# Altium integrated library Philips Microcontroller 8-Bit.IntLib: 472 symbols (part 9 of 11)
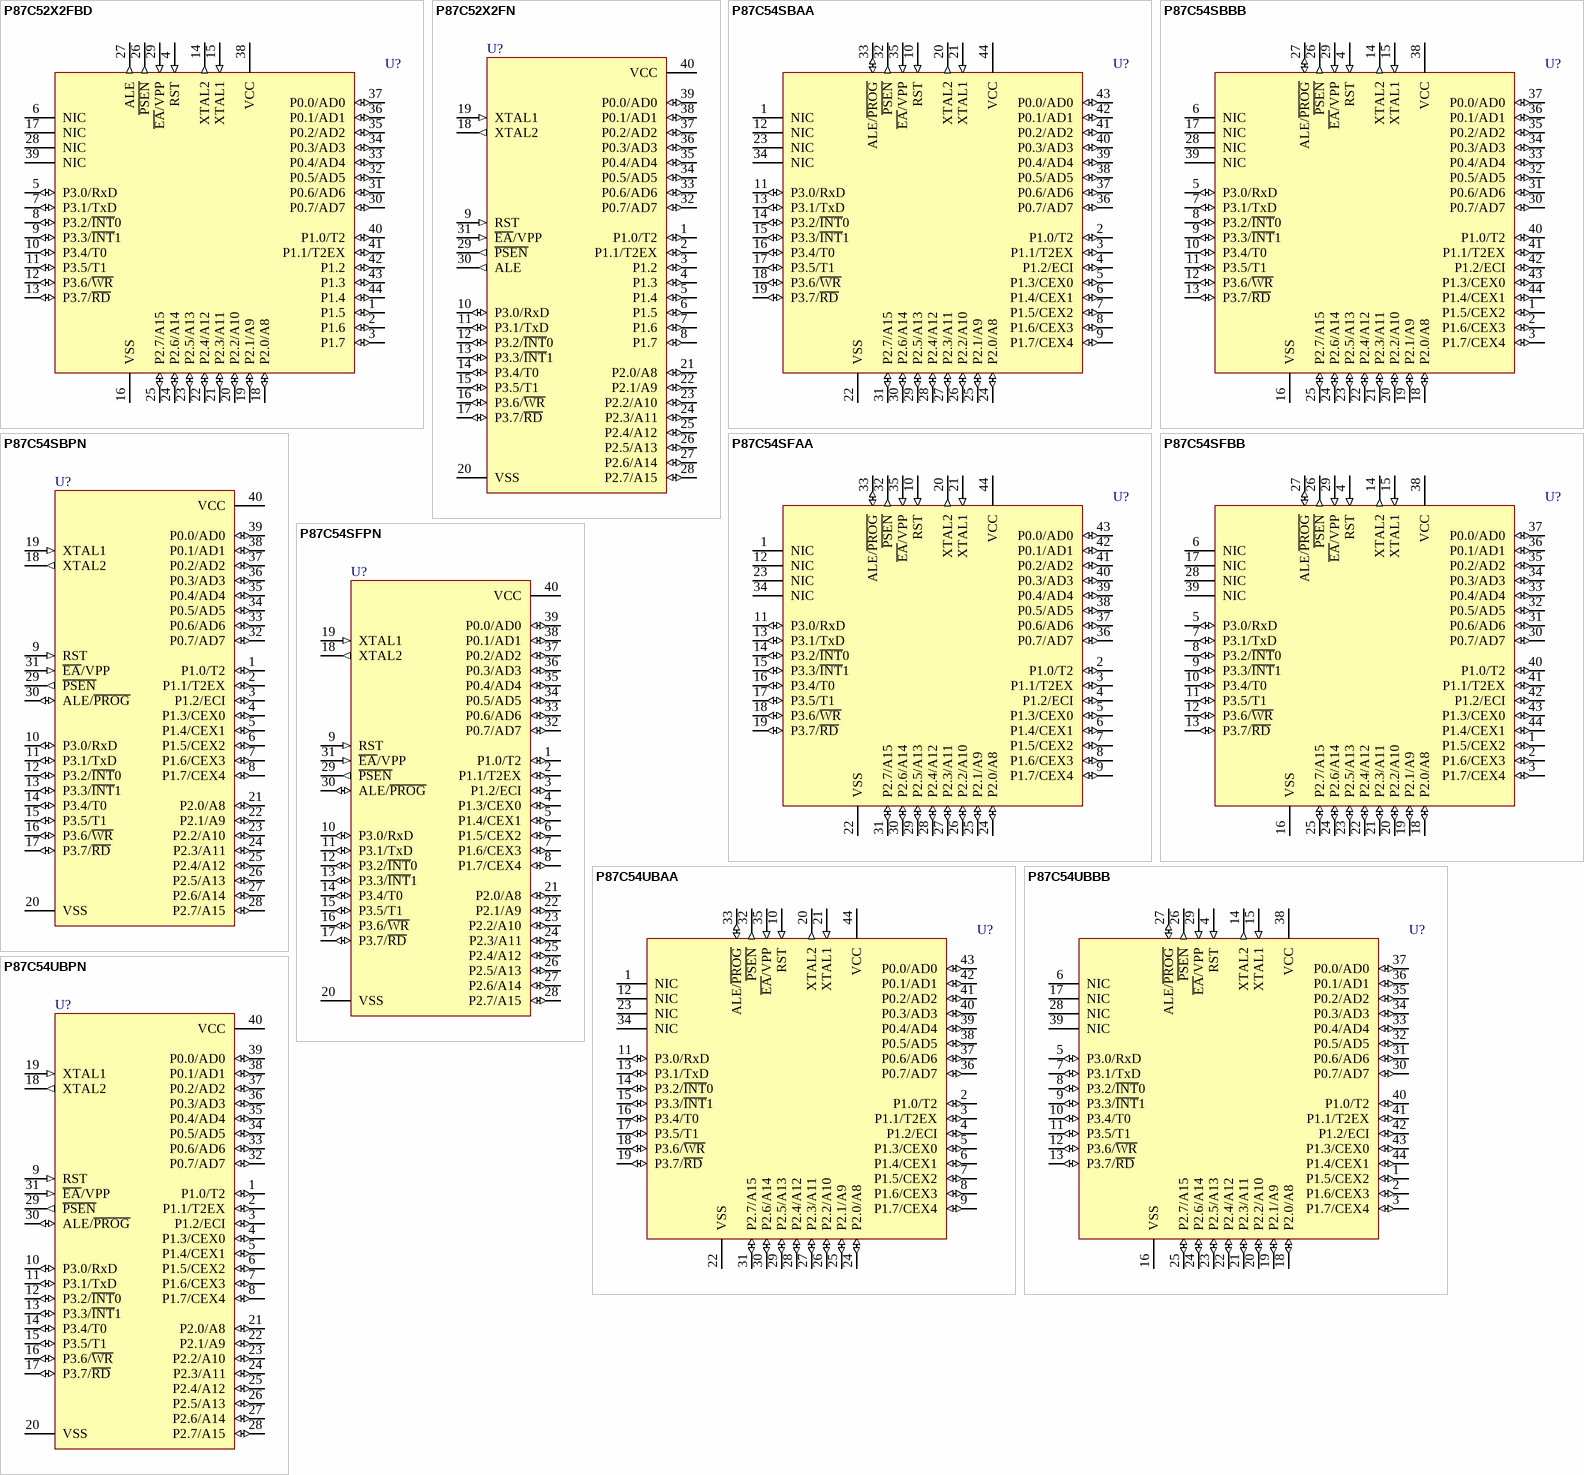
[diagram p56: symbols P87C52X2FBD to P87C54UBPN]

## P87C54SFBB
designator U?
80C51 8-Bit Microcontroller Family: 256 B RAM, 16 kB OTP, 2.7V-5.5V, Low Power, High Speed
footprint SOT307-2_N (QFP, 44-Leads, Body 10x10mm, Pitch 0.8mm, IPC Medium Density)
footprint SOT307-2_L (QFP, 44-Leads, Body 10x10mm, Pitch 0.8mm, IPC High Density)
footprint SOT307-2_M (QFP, 44-Leads, Body 10x10mm, Pitch 0.8mm, IPC Low Density)
pins: 1 P1.5/CEX2 (io), 2 P1.6/CEX3 (io), 3 P1.7/CEX4 (io), 4 RST (in), 5 P3.0/RxD (io), 6 NIC, 7 P3.1/TxD (io), 8 P3.2/~{INT}0 (io), 9 P3.3/~{INT}1 (io), 10 P3.4/T0 (io), 11 P3.5/T1 (io), 12 P3.6/~{WR} (io), 13 P3.7/~{RD} (io), 14 XTAL2 (out), 15 XTAL1 (in), 16 VSS (power), 17 NIC, 18 P2.0/A8 (io), 19 P2.1/A9 (io), 20 P2.2/A10 (io), 21 P2.3/A11 (io), 22 P2.4/A12 (io), 23 P2.5/A13 (io), 24 P2.6/A14 (io), 25 P2.7/A15 (io), 26 ~{PSEN} (out), 27 ALE/~{PROG} (io), 28 NIC, 29 ~{EA}/VPP (in), 30 P0.7/AD7 (io), 31 P0.6/AD6 (io), 32 P0.5/AD5 (io), 33 P0.4/AD4 (io), 34 P0.3/AD3 (io), 35 P0.2/AD2 (io), 36 P0.1/AD1 (io), 37 P0.0/AD0 (io), 38 VCC (power), 39 NIC, 40 P1.0/T2 (io), 41 P1.1/T2EX (io), 42 P1.2/ECI (io), 43 P1.3/CEX0 (io), 44 P1.4/CEX1 (io)

## P87C54SFPN
designator U?
80C51 8-Bit Microcontroller Family: 256 B RAM, 16 kB OTP, 2.7V-5.5V, Low Power, High Speed
footprint SOT129-1 (DIP, Plastic; 40 Leads; Row Spacing 15.24 mm; Pitch 2.54 mm)
pins: 1 P1.0/T2 (io), 2 P1.1/T2EX (io), 3 P1.2/ECI (io), 4 P1.3/CEX0 (io), 5 P1.4/CEX1 (io), 6 P1.5/CEX2 (io), 7 P1.6/CEX3 (io), 8 P1.7/CEX4 (io), 9 RST (in), 10 P3.0/RxD (io), 11 P3.1/TxD (io), 12 P3.2/~{INT}0 (io), 13 P3.3/~{INT}1 (io), 14 P3.4/T0 (io), 15 P3.5/T1 (io), 16 P3.6/~{WR} (io), 17 P3.7/~{RD} (io), 18 XTAL2 (out), 19 XTAL1 (in), 20 VSS (power), 21 P2.0/A8 (io), 22 P2.1/A9 (io), 23 P2.2/A10 (io), 24 P2.3/A11 (io), 25 P2.4/A12 (io), 26 P2.5/A13 (io), 27 P2.6/A14 (io), 28 P2.7/A15 (io), 29 ~{PSEN} (out), 30 ALE/~{PROG} (io), 31 ~{EA}/VPP (in), 32 P0.7/AD7 (io), 33 P0.6/AD6 (io), 34 P0.5/AD5 (io), 35 P0.4/AD4 (io), 36 P0.3/AD3 (io), 37 P0.2/AD2 (io), 38 P0.1/AD1 (io), 39 P0.0/AD0 (io), 40 VCC (power)

## P87C54UBAA
designator U?
80C51 8-Bit Microcontroller Family: 256 B RAM, 16 kB OTP, 5V, Low Power, High Speed
footprint SOT187-2_N (Leaded Chip Carrier, 44-Leads, Body 16.6x16.6mm, Pitch 1.27mm, IPC Medium Density)
footprint SOT187-2_L (Leaded Chip Carrier, 44-Leads, Body 16.6x16.6mm, Pitch 1.27mm, IPC High Density)
footprint SOT187-2_M (Leaded Chip Carrier, 44-Leads, Body 16.6x16.6mm, Pitch 1.27mm, IPC Low Density)
pins: 1 NIC, 2 P1.0/T2 (io), 3 P1.1/T2EX (io), 4 P1.2/ECI (io), 5 P1.3/CEX0 (io), 6 P1.4/CEX1 (io), 7 P1.5/CEX2 (io), 8 P1.6/CEX3 (io), 9 P1.7/CEX4 (io), 10 RST (in), 11 P3.0/RxD (io), 12 NIC, 13 P3.1/TxD (io), 14 P3.2/~{INT}0 (io), 15 P3.3/~{INT}1 (io), 16 P3.4/T0 (io), 17 P3.5/T1 (io), 18 P3.6/~{WR} (io), 19 P3.7/~{RD} (io), 20 XTAL2 (out), 21 XTAL1 (in), 22 VSS (power), 23 NIC, 24 P2.0/A8 (io), 25 P2.1/A9 (io), 26 P2.2/A10 (io), 27 P2.3/A11 (io), 28 P2.4/A12 (io), 29 P2.5/A13 (io), 30 P2.6/A14 (io), 31 P2.7/A15 (io), 32 ~{PSEN} (out), 33 ALE/~{PROG} (io), 34 NIC, 35 ~{EA}/VPP (in), 36 P0.7/AD7 (io), 37 P0.6/AD6 (io), 38 P0.5/AD5 (io), 39 P0.4/AD4 (io), 40 P0.3/AD3 (io), 41 P0.2/AD2 (io), 42 P0.1/AD1 (io), 43 P0.0/AD0 (io), 44 VCC (power)

## P87C54UBBB
designator U?
80C51 8-Bit Microcontroller Family: 256 B RAM, 16 kB OTP, 5V, Low Power, High Speed
footprint SOT307-2_N (QFP, 44-Leads, Body 10x10mm, Pitch 0.8mm, IPC Medium Density)
footprint SOT307-2_L (QFP, 44-Leads, Body 10x10mm, Pitch 0.8mm, IPC High Density)
footprint SOT307-2_M (QFP, 44-Leads, Body 10x10mm, Pitch 0.8mm, IPC Low Density)
pins: 1 P1.5/CEX2 (io), 2 P1.6/CEX3 (io), 3 P1.7/CEX4 (io), 4 RST (in), 5 P3.0/RxD (io), 6 NIC, 7 P3.1/TxD (io), 8 P3.2/~{INT}0 (io), 9 P3.3/~{INT}1 (io), 10 P3.4/T0 (io), 11 P3.5/T1 (io), 12 P3.6/~{WR} (io), 13 P3.7/~{RD} (io), 14 XTAL2 (out), 15 XTAL1 (in), 16 VSS (power), 17 NIC, 18 P2.0/A8 (io), 19 P2.1/A9 (io), 20 P2.2/A10 (io), 21 P2.3/A11 (io), 22 P2.4/A12 (io), 23 P2.5/A13 (io), 24 P2.6/A14 (io), 25 P2.7/A15 (io), 26 ~{PSEN} (out), 27 ALE/~{PROG} (io), 28 NIC, 29 ~{EA}/VPP (in), 30 P0.7/AD7 (io), 31 P0.6/AD6 (io), 32 P0.5/AD5 (io), 33 P0.4/AD4 (io), 34 P0.3/AD3 (io), 35 P0.2/AD2 (io), 36 P0.1/AD1 (io), 37 P0.0/AD0 (io), 38 VCC (power), 39 NIC, 40 P1.0/T2 (io), 41 P1.1/T2EX (io), 42 P1.2/ECI (io), 43 P1.3/CEX0 (io), 44 P1.4/CEX1 (io)

## P87C54UBPN
designator U?
80C51 8-Bit Microcontroller Family: 256 B RAM, 16 kB OTP, 5V, Low Power, High Speed
footprint SOT129-1 (DIP, Plastic; 40 Leads; Row Spacing 15.24 mm; Pitch 2.54 mm)
pins: 1 P1.0/T2 (io), 2 P1.1/T2EX (io), 3 P1.2/ECI (io), 4 P1.3/CEX0 (io), 5 P1.4/CEX1 (io), 6 P1.5/CEX2 (io), 7 P1.6/CEX3 (io), 8 P1.7/CEX4 (io), 9 RST (in), 10 P3.0/RxD (io), 11 P3.1/TxD (io), 12 P3.2/~{INT}0 (io), 13 P3.3/~{INT}1 (io), 14 P3.4/T0 (io), 15 P3.5/T1 (io), 16 P3.6/~{WR} (io), 17 P3.7/~{RD} (io), 18 XTAL2 (out), 19 XTAL1 (in), 20 VSS (power), 21 P2.0/A8 (io), 22 P2.1/A9 (io), 23 P2.2/A10 (io), 24 P2.3/A11 (io), 25 P2.4/A12 (io), 26 P2.5/A13 (io), 27 P2.6/A14 (io), 28 P2.7/A15 (io), 29 ~{PSEN} (out), 30 ALE/~{PROG} (io), 31 ~{EA}/VPP (in), 32 P0.7/AD7 (io), 33 P0.6/AD6 (io), 34 P0.5/AD5 (io), 35 P0.4/AD4 (io), 36 P0.3/AD3 (io), 37 P0.2/AD2 (io), 38 P0.1/AD1 (io), 39 P0.0/AD0 (io), 40 VCC (power)

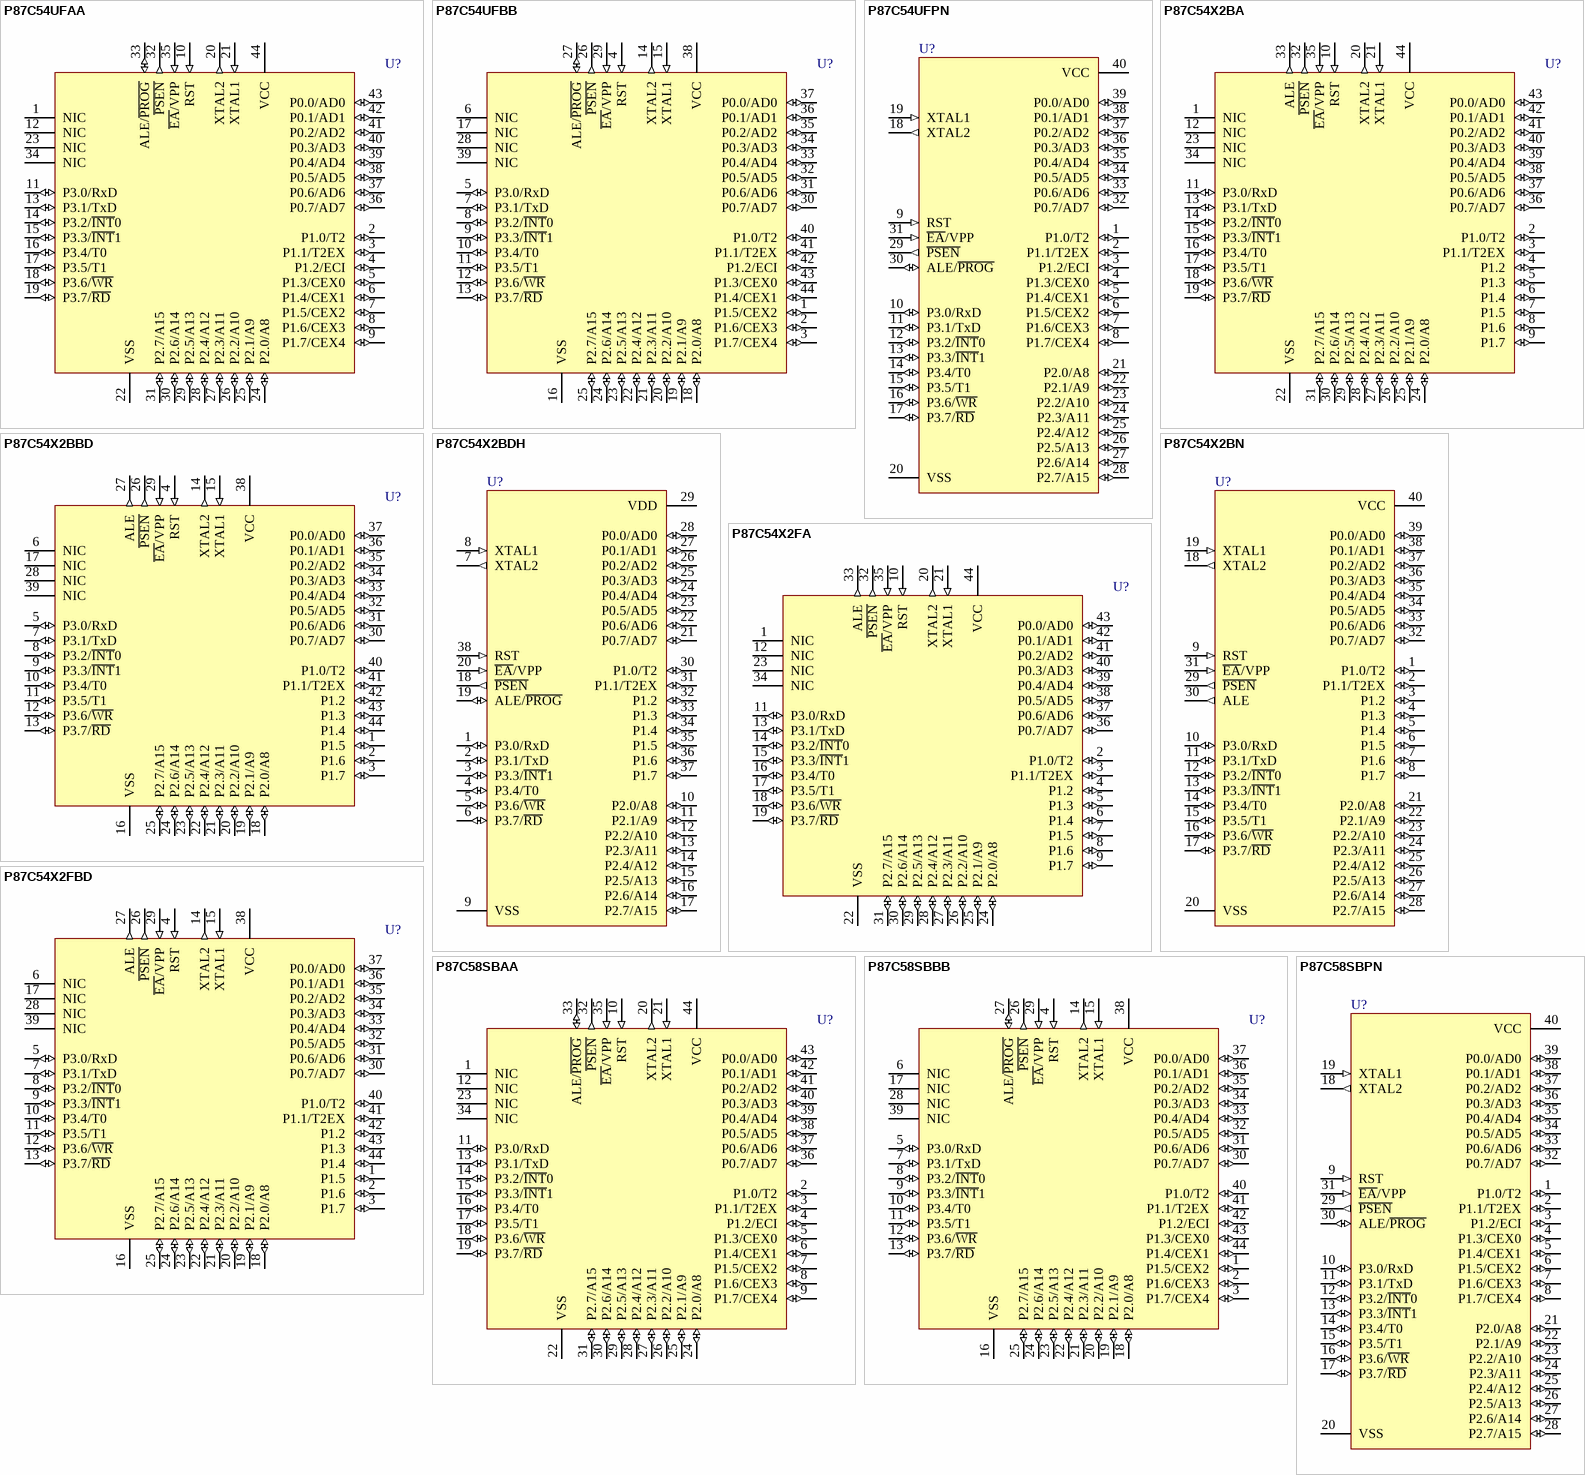
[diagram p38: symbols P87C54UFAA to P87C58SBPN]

## P87C54UFAA
designator U?
80C51 8-Bit Microcontroller Family: 256 B RAM, 16 kB OTP, 5V, Low Power, High Speed
footprint SOT187-2_N (Leaded Chip Carrier, 44-Leads, Body 16.6x16.6mm, Pitch 1.27mm, IPC Medium Density)
footprint SOT187-2_L (Leaded Chip Carrier, 44-Leads, Body 16.6x16.6mm, Pitch 1.27mm, IPC High Density)
footprint SOT187-2_M (Leaded Chip Carrier, 44-Leads, Body 16.6x16.6mm, Pitch 1.27mm, IPC Low Density)
pins: 1 NIC, 2 P1.0/T2 (io), 3 P1.1/T2EX (io), 4 P1.2/ECI (io), 5 P1.3/CEX0 (io), 6 P1.4/CEX1 (io), 7 P1.5/CEX2 (io), 8 P1.6/CEX3 (io), 9 P1.7/CEX4 (io), 10 RST (in), 11 P3.0/RxD (io), 12 NIC, 13 P3.1/TxD (io), 14 P3.2/~{INT}0 (io), 15 P3.3/~{INT}1 (io), 16 P3.4/T0 (io), 17 P3.5/T1 (io), 18 P3.6/~{WR} (io), 19 P3.7/~{RD} (io), 20 XTAL2 (out), 21 XTAL1 (in), 22 VSS (power), 23 NIC, 24 P2.0/A8 (io), 25 P2.1/A9 (io), 26 P2.2/A10 (io), 27 P2.3/A11 (io), 28 P2.4/A12 (io), 29 P2.5/A13 (io), 30 P2.6/A14 (io), 31 P2.7/A15 (io), 32 ~{PSEN} (out), 33 ALE/~{PROG} (io), 34 NIC, 35 ~{EA}/VPP (in), 36 P0.7/AD7 (io), 37 P0.6/AD6 (io), 38 P0.5/AD5 (io), 39 P0.4/AD4 (io), 40 P0.3/AD3 (io), 41 P0.2/AD2 (io), 42 P0.1/AD1 (io), 43 P0.0/AD0 (io), 44 VCC (power)

## P87C54UFBB
designator U?
80C51 8-Bit Microcontroller Family: 256 B RAM, 16 kB OTP, 5V, Low Power, High Speed
footprint SOT307-2_N (QFP, 44-Leads, Body 10x10mm, Pitch 0.8mm, IPC Medium Density)
footprint SOT307-2_L (QFP, 44-Leads, Body 10x10mm, Pitch 0.8mm, IPC High Density)
footprint SOT307-2_M (QFP, 44-Leads, Body 10x10mm, Pitch 0.8mm, IPC Low Density)
pins: 1 P1.5/CEX2 (io), 2 P1.6/CEX3 (io), 3 P1.7/CEX4 (io), 4 RST (in), 5 P3.0/RxD (io), 6 NIC, 7 P3.1/TxD (io), 8 P3.2/~{INT}0 (io), 9 P3.3/~{INT}1 (io), 10 P3.4/T0 (io), 11 P3.5/T1 (io), 12 P3.6/~{WR} (io), 13 P3.7/~{RD} (io), 14 XTAL2 (out), 15 XTAL1 (in), 16 VSS (power), 17 NIC, 18 P2.0/A8 (io), 19 P2.1/A9 (io), 20 P2.2/A10 (io), 21 P2.3/A11 (io), 22 P2.4/A12 (io), 23 P2.5/A13 (io), 24 P2.6/A14 (io), 25 P2.7/A15 (io), 26 ~{PSEN} (out), 27 ALE/~{PROG} (io), 28 NIC, 29 ~{EA}/VPP (in), 30 P0.7/AD7 (io), 31 P0.6/AD6 (io), 32 P0.5/AD5 (io), 33 P0.4/AD4 (io), 34 P0.3/AD3 (io), 35 P0.2/AD2 (io), 36 P0.1/AD1 (io), 37 P0.0/AD0 (io), 38 VCC (power), 39 NIC, 40 P1.0/T2 (io), 41 P1.1/T2EX (io), 42 P1.2/ECI (io), 43 P1.3/CEX0 (io), 44 P1.4/CEX1 (io)

## P87C54UFPN
designator U?
80C51 8-Bit Microcontroller Family: 256 B RAM, 16 kB OTP, 5V, Low Power, High Speed
footprint SOT129-1 (DIP, Plastic; 40 Leads; Row Spacing 15.24 mm; Pitch 2.54 mm)
pins: 1 P1.0/T2 (io), 2 P1.1/T2EX (io), 3 P1.2/ECI (io), 4 P1.3/CEX0 (io), 5 P1.4/CEX1 (io), 6 P1.5/CEX2 (io), 7 P1.6/CEX3 (io), 8 P1.7/CEX4 (io), 9 RST (in), 10 P3.0/RxD (io), 11 P3.1/TxD (io), 12 P3.2/~{INT}0 (io), 13 P3.3/~{INT}1 (io), 14 P3.4/T0 (io), 15 P3.5/T1 (io), 16 P3.6/~{WR} (io), 17 P3.7/~{RD} (io), 18 XTAL2 (out), 19 XTAL1 (in), 20 VSS (power), 21 P2.0/A8 (io), 22 P2.1/A9 (io), 23 P2.2/A10 (io), 24 P2.3/A11 (io), 25 P2.4/A12 (io), 26 P2.5/A13 (io), 27 P2.6/A14 (io), 28 P2.7/A15 (io), 29 ~{PSEN} (out), 30 ALE/~{PROG} (io), 31 ~{EA}/VPP (in), 32 P0.7/AD7 (io), 33 P0.6/AD6 (io), 34 P0.5/AD5 (io), 35 P0.4/AD4 (io), 36 P0.3/AD3 (io), 37 P0.2/AD2 (io), 38 P0.1/AD1 (io), 39 P0.0/AD0 (io), 40 VCC (power)

## P87C54X2BA
designator U?
80C51 8-Bit Microcontroller Family: 256 B RAM, 16 kB OTP, 2.7 to 5.5 V, Low Power, High Speed
footprint SOT187-2_N (Leaded Chip Carrier, 44-Leads, Body 16.6x16.6mm, Pitch 1.27mm, IPC Medium Density)
footprint SOT187-2_L (Leaded Chip Carrier, 44-Leads, Body 16.6x16.6mm, Pitch 1.27mm, IPC High Density)
footprint SOT187-2_M (Leaded Chip Carrier, 44-Leads, Body 16.6x16.6mm, Pitch 1.27mm, IPC Low Density)
pins: 1 NIC, 2 P1.0/T2 (io), 3 P1.1/T2EX (io), 4 P1.2 (io), 5 P1.3 (io), 6 P1.4 (io), 7 P1.5 (io), 8 P1.6 (io), 9 P1.7 (io), 10 RST (in), 11 P3.0/RxD (io), 12 NIC, 13 P3.1/TxD (io), 14 P3.2/~{INT}0 (io), 15 P3.3/~{INT}1 (io), 16 P3.4/T0 (io), 17 P3.5/T1 (io), 18 P3.6/~{WR} (io), 19 P3.7/~{RD} (io), 20 XTAL2 (out), 21 XTAL1 (in), 22 VSS (power), 23 NIC, 24 P2.0/A8 (io), 25 P2.1/A9 (io), 26 P2.2/A10 (io), 27 P2.3/A11 (io), 28 P2.4/A12 (io), 29 P2.5/A13 (io), 30 P2.6/A14 (io), 31 P2.7/A15 (io), 32 ~{PSEN} (out), 33 ALE (out), 34 NIC, 35 ~{EA}/VPP (in), 36 P0.7/AD7 (io), 37 P0.6/AD6 (io), 38 P0.5/AD5 (io), 39 P0.4/AD4 (io), 40 P0.3/AD3 (io), 41 P0.2/AD2 (io), 42 P0.1/AD1 (io), 43 P0.0/AD0 (io), 44 VCC (power)

## P87C54X2BBD
designator U?
80C51 8-Bit Microcontroller Family: 256 B RAM, 16 kB OTP, 2.7 to 5.5 V, Low Power, High Speed
footprint SOT389-1_N (Thin QFP, 44-Leads, Body 10x10mm, Pitch 0.8mm, IPC Medium Density)
footprint SOT389-1_L (Thin QFP, 44-Leads, Body 10x10mm, Pitch 0.8mm, IPC High Density)
footprint SOT389-1_M (Thin QFP, 44-Leads, Body 10x10mm, Pitch 0.8mm, IPC Low Density)
pins: 1 P1.5 (io), 2 P1.6 (io), 3 P1.7 (io), 4 RST (in), 5 P3.0/RxD (io), 6 NIC, 7 P3.1/TxD (io), 8 P3.2/~{INT}0 (io), 9 P3.3/~{INT}1 (io), 10 P3.4/T0 (io), 11 P3.5/T1 (io), 12 P3.6/~{WR} (io), 13 P3.7/~{RD} (io), 14 XTAL2 (out), 15 XTAL1 (in), 16 VSS (power), 17 NIC, 18 P2.0/A8 (io), 19 P2.1/A9 (io), 20 P2.2/A10 (io), 21 P2.3/A11 (io), 22 P2.4/A12 (io), 23 P2.5/A13 (io), 24 P2.6/A14 (io), 25 P2.7/A15 (io), 26 ~{PSEN} (out), 27 ALE (out), 28 NIC, 29 ~{EA}/VPP (in), 30 P0.7/AD7 (io), 31 P0.6/AD6 (io), 32 P0.5/AD5 (io), 33 P0.4/AD4 (io), 34 P0.3/AD3 (io), 35 P0.2/AD2 (io), 36 P0.1/AD1 (io), 37 P0.0/AD0 (io), 38 VCC (power), 39 NIC, 40 P1.0/T2 (io), 41 P1.1/T2EX (io), 42 P1.2 (io), 43 P1.3 (io), 44 P1.4 (io)

## P87C54X2BDH
designator U?
80C51 8-Bit Microcontroller Family: 256 B RAM, 16 kB OTP, 2.7 to 5.5 V, Low Power, High Speed
footprint SOT510-1 (Shrink Small Outline; 38 Leads; Body Width 4.4 mm; Pitch 0.5 mm)
pins: 1 P3.0/RxD (io), 2 P3.1/TxD (io), 3 P3.3/~{INT}1 (io), 4 P3.4/T0 (io), 5 P3.6/~{WR} (io), 6 P3.7/~{RD} (io), 7 XTAL2 (out), 8 XTAL1 (in), 9 VSS (power), 10 P2.0/A8 (io), 11 P2.1/A9 (io), 12 P2.2/A10 (io), 13 P2.3/A11 (io), 14 P2.4/A12 (io), 15 P2.5/A13 (io), 16 P2.6/A14 (io), 17 P2.7/A15 (io), 18 ~{PSEN} (out), 19 ALE/~{PROG} (io), 20 ~{EA}/VPP (in), 21 P0.7/AD7 (io), 22 P0.6/AD6 (io), 23 P0.5/AD5 (io), 24 P0.4/AD4 (io), 25 P0.3/AD3 (io), 26 P0.2/AD2 (io), 27 P0.1/AD1 (io), 28 P0.0/AD0 (io), 29 VDD (power), 30 P1.0/T2 (io), 31 P1.1/T2EX (io), 32 P1.2 (io), 33 P1.3 (io), 34 P1.4 (io), 35 P1.5 (io), 36 P1.6 (io), 37 P1.7 (io), 38 RST (in)

## P87C54X2BN
designator U?
80C51 8-Bit Microcontroller Family: 256 B RAM, 16 kB OTP, 2.7 to 5.5 V, Low Power, High Speed
footprint SOT129-1 (DIP, Plastic; 40 Leads; Row Spacing 15.24 mm; Pitch 2.54 mm)
pins: 1 P1.0/T2 (io), 2 P1.1/T2EX (io), 3 P1.2 (io), 4 P1.3 (io), 5 P1.4 (io), 6 P1.5 (io), 7 P1.6 (io), 8 P1.7 (io), 9 RST (in), 10 P3.0/RxD (io), 11 P3.1/TxD (io), 12 P3.2/~{INT}0 (io), 13 P3.3/~{INT}1 (io), 14 P3.4/T0 (io), 15 P3.5/T1 (io), 16 P3.6/~{WR} (io), 17 P3.7/~{RD} (io), 18 XTAL2 (out), 19 XTAL1 (in), 20 VSS (power), 21 P2.0/A8 (io), 22 P2.1/A9 (io), 23 P2.2/A10 (io), 24 P2.3/A11 (io), 25 P2.4/A12 (io), 26 P2.5/A13 (io), 27 P2.6/A14 (io), 28 P2.7/A15 (io), 29 ~{PSEN} (out), 30 ALE (out), 31 ~{EA}/VPP (in), 32 P0.7/AD7 (io), 33 P0.6/AD6 (io), 34 P0.5/AD5 (io), 35 P0.4/AD4 (io), 36 P0.3/AD3 (io), 37 P0.2/AD2 (io), 38 P0.1/AD1 (io), 39 P0.0/AD0 (io), 40 VCC (power)

## P87C54X2FA
designator U?
80C51 8-Bit Microcontroller Family: 256 B RAM, 16 kB OTP, 2.7 to 5.5 V, Low Power, High Speed
footprint SOT187-2_N (Leaded Chip Carrier, 44-Leads, Body 16.6x16.6mm, Pitch 1.27mm, IPC Medium Density)
footprint SOT187-2_L (Leaded Chip Carrier, 44-Leads, Body 16.6x16.6mm, Pitch 1.27mm, IPC High Density)
footprint SOT187-2_M (Leaded Chip Carrier, 44-Leads, Body 16.6x16.6mm, Pitch 1.27mm, IPC Low Density)
pins: 1 NIC, 2 P1.0/T2 (io), 3 P1.1/T2EX (io), 4 P1.2 (io), 5 P1.3 (io), 6 P1.4 (io), 7 P1.5 (io), 8 P1.6 (io), 9 P1.7 (io), 10 RST (in), 11 P3.0/RxD (io), 12 NIC, 13 P3.1/TxD (io), 14 P3.2/~{INT}0 (io), 15 P3.3/~{INT}1 (io), 16 P3.4/T0 (io), 17 P3.5/T1 (io), 18 P3.6/~{WR} (io), 19 P3.7/~{RD} (io), 20 XTAL2 (out), 21 XTAL1 (in), 22 VSS (power), 23 NIC, 24 P2.0/A8 (io), 25 P2.1/A9 (io), 26 P2.2/A10 (io), 27 P2.3/A11 (io), 28 P2.4/A12 (io), 29 P2.5/A13 (io), 30 P2.6/A14 (io), 31 P2.7/A15 (io), 32 ~{PSEN} (out), 33 ALE (out), 34 NIC, 35 ~{EA}/VPP (in), 36 P0.7/AD7 (io), 37 P0.6/AD6 (io), 38 P0.5/AD5 (io), 39 P0.4/AD4 (io), 40 P0.3/AD3 (io), 41 P0.2/AD2 (io), 42 P0.1/AD1 (io), 43 P0.0/AD0 (io), 44 VCC (power)

## P87C54X2FBD
designator U?
80C51 8-Bit Microcontroller Family: 256 B RAM, 16 kB OTP, 2.7 to 5.5 V, Low Power, High Speed
footprint SOT389-1_N (Thin QFP, 44-Leads, Body 10x10mm, Pitch 0.8mm, IPC Medium Density)
footprint SOT389-1_L (Thin QFP, 44-Leads, Body 10x10mm, Pitch 0.8mm, IPC High Density)
footprint SOT389-1_M (Thin QFP, 44-Leads, Body 10x10mm, Pitch 0.8mm, IPC Low Density)
pins: 1 P1.5 (io), 2 P1.6 (io), 3 P1.7 (io), 4 RST (in), 5 P3.0/RxD (io), 6 NIC, 7 P3.1/TxD (io), 8 P3.2/~{INT}0 (io), 9 P3.3/~{INT}1 (io), 10 P3.4/T0 (io), 11 P3.5/T1 (io), 12 P3.6/~{WR} (io), 13 P3.7/~{RD} (io), 14 XTAL2 (out), 15 XTAL1 (in), 16 VSS (power), 17 NIC, 18 P2.0/A8 (io), 19 P2.1/A9 (io), 20 P2.2/A10 (io), 21 P2.3/A11 (io), 22 P2.4/A12 (io), 23 P2.5/A13 (io), 24 P2.6/A14 (io), 25 P2.7/A15 (io), 26 ~{PSEN} (out), 27 ALE (out), 28 NIC, 29 ~{EA}/VPP (in), 30 P0.7/AD7 (io), 31 P0.6/AD6 (io), 32 P0.5/AD5 (io), 33 P0.4/AD4 (io), 34 P0.3/AD3 (io), 35 P0.2/AD2 (io), 36 P0.1/AD1 (io), 37 P0.0/AD0 (io), 38 VCC (power), 39 NIC, 40 P1.0/T2 (io), 41 P1.1/T2EX (io), 42 P1.2 (io), 43 P1.3 (io), 44 P1.4 (io)

## P87C58SBAA
designator U?
80C51 8-Bit Microcontroller Family: 256 B RAM, 32 kB OTP, 2.7V-5.5V, Low Power, High Speed
footprint SOT187-2_N (Leaded Chip Carrier, 44-Leads, Body 16.6x16.6mm, Pitch 1.27mm, IPC Medium Density)
footprint SOT187-2_L (Leaded Chip Carrier, 44-Leads, Body 16.6x16.6mm, Pitch 1.27mm, IPC High Density)
footprint SOT187-2_M (Leaded Chip Carrier, 44-Leads, Body 16.6x16.6mm, Pitch 1.27mm, IPC Low Density)
pins: 1 NIC, 2 P1.0/T2 (io), 3 P1.1/T2EX (io), 4 P1.2/ECI (io), 5 P1.3/CEX0 (io), 6 P1.4/CEX1 (io), 7 P1.5/CEX2 (io), 8 P1.6/CEX3 (io), 9 P1.7/CEX4 (io), 10 RST (in), 11 P3.0/RxD (io), 12 NIC, 13 P3.1/TxD (io), 14 P3.2/~{INT}0 (io), 15 P3.3/~{INT}1 (io), 16 P3.4/T0 (io), 17 P3.5/T1 (io), 18 P3.6/~{WR} (io), 19 P3.7/~{RD} (io), 20 XTAL2 (out), 21 XTAL1 (in), 22 VSS (power), 23 NIC, 24 P2.0/A8 (io), 25 P2.1/A9 (io), 26 P2.2/A10 (io), 27 P2.3/A11 (io), 28 P2.4/A12 (io), 29 P2.5/A13 (io), 30 P2.6/A14 (io), 31 P2.7/A15 (io), 32 ~{PSEN} (out), 33 ALE/~{PROG} (io), 34 NIC, 35 ~{EA}/VPP (in), 36 P0.7/AD7 (io), 37 P0.6/AD6 (io), 38 P0.5/AD5 (io), 39 P0.4/AD4 (io), 40 P0.3/AD3 (io), 41 P0.2/AD2 (io), 42 P0.1/AD1 (io), 43 P0.0/AD0 (io), 44 VCC (power)

## P87C58SBBB
designator U?
80C51 8-Bit Microcontroller Family: 256 B RAM, 32 kB OTP, 2.7V-5.5V, Low Power, High Speed
footprint SOT307-2_N (QFP, 44-Leads, Body 10x10mm, Pitch 0.8mm, IPC Medium Density)
footprint SOT307-2_L (QFP, 44-Leads, Body 10x10mm, Pitch 0.8mm, IPC High Density)
footprint SOT307-2_M (QFP, 44-Leads, Body 10x10mm, Pitch 0.8mm, IPC Low Density)
pins: 1 P1.5/CEX2 (io), 2 P1.6/CEX3 (io), 3 P1.7/CEX4 (io), 4 RST (in), 5 P3.0/RxD (io), 6 NIC, 7 P3.1/TxD (io), 8 P3.2/~{INT}0 (io), 9 P3.3/~{INT}1 (io), 10 P3.4/T0 (io), 11 P3.5/T1 (io), 12 P3.6/~{WR} (io), 13 P3.7/~{RD} (io), 14 XTAL2 (out), 15 XTAL1 (in), 16 VSS (power), 17 NIC, 18 P2.0/A8 (io), 19 P2.1/A9 (io), 20 P2.2/A10 (io), 21 P2.3/A11 (io), 22 P2.4/A12 (io), 23 P2.5/A13 (io), 24 P2.6/A14 (io), 25 P2.7/A15 (io), 26 ~{PSEN} (out), 27 ALE/~{PROG} (io), 28 NIC, 29 ~{EA}/VPP (in), 30 P0.7/AD7 (io), 31 P0.6/AD6 (io), 32 P0.5/AD5 (io), 33 P0.4/AD4 (io), 34 P0.3/AD3 (io), 35 P0.2/AD2 (io), 36 P0.1/AD1 (io), 37 P0.0/AD0 (io), 38 VCC (power), 39 NIC, 40 P1.0/T2 (io), 41 P1.1/T2EX (io), 42 P1.2/ECI (io), 43 P1.3/CEX0 (io), 44 P1.4/CEX1 (io)

## P87C58SBPN
designator U?
80C51 8-Bit Microcontroller Family: 256 B RAM, 32 kB OTP, 2.7V-5.5V, Low Power, High Speed
footprint SOT129-1 (DIP, Plastic; 40 Leads; Row Spacing 15.24 mm; Pitch 2.54 mm)
pins: 1 P1.0/T2 (io), 2 P1.1/T2EX (io), 3 P1.2/ECI (io), 4 P1.3/CEX0 (io), 5 P1.4/CEX1 (io), 6 P1.5/CEX2 (io), 7 P1.6/CEX3 (io), 8 P1.7/CEX4 (io), 9 RST (in), 10 P3.0/RxD (io), 11 P3.1/TxD (io), 12 P3.2/~{INT}0 (io), 13 P3.3/~{INT}1 (io), 14 P3.4/T0 (io), 15 P3.5/T1 (io), 16 P3.6/~{WR} (io), 17 P3.7/~{RD} (io), 18 XTAL2 (out), 19 XTAL1 (in), 20 VSS (power), 21 P2.0/A8 (io), 22 P2.1/A9 (io), 23 P2.2/A10 (io), 24 P2.3/A11 (io), 25 P2.4/A12 (io), 26 P2.5/A13 (io), 27 P2.6/A14 (io), 28 P2.7/A15 (io), 29 ~{PSEN} (out), 30 ALE/~{PROG} (io), 31 ~{EA}/VPP (in), 32 P0.7/AD7 (io), 33 P0.6/AD6 (io), 34 P0.5/AD5 (io), 35 P0.4/AD4 (io), 36 P0.3/AD3 (io), 37 P0.2/AD2 (io), 38 P0.1/AD1 (io), 39 P0.0/AD0 (io), 40 VCC (power)

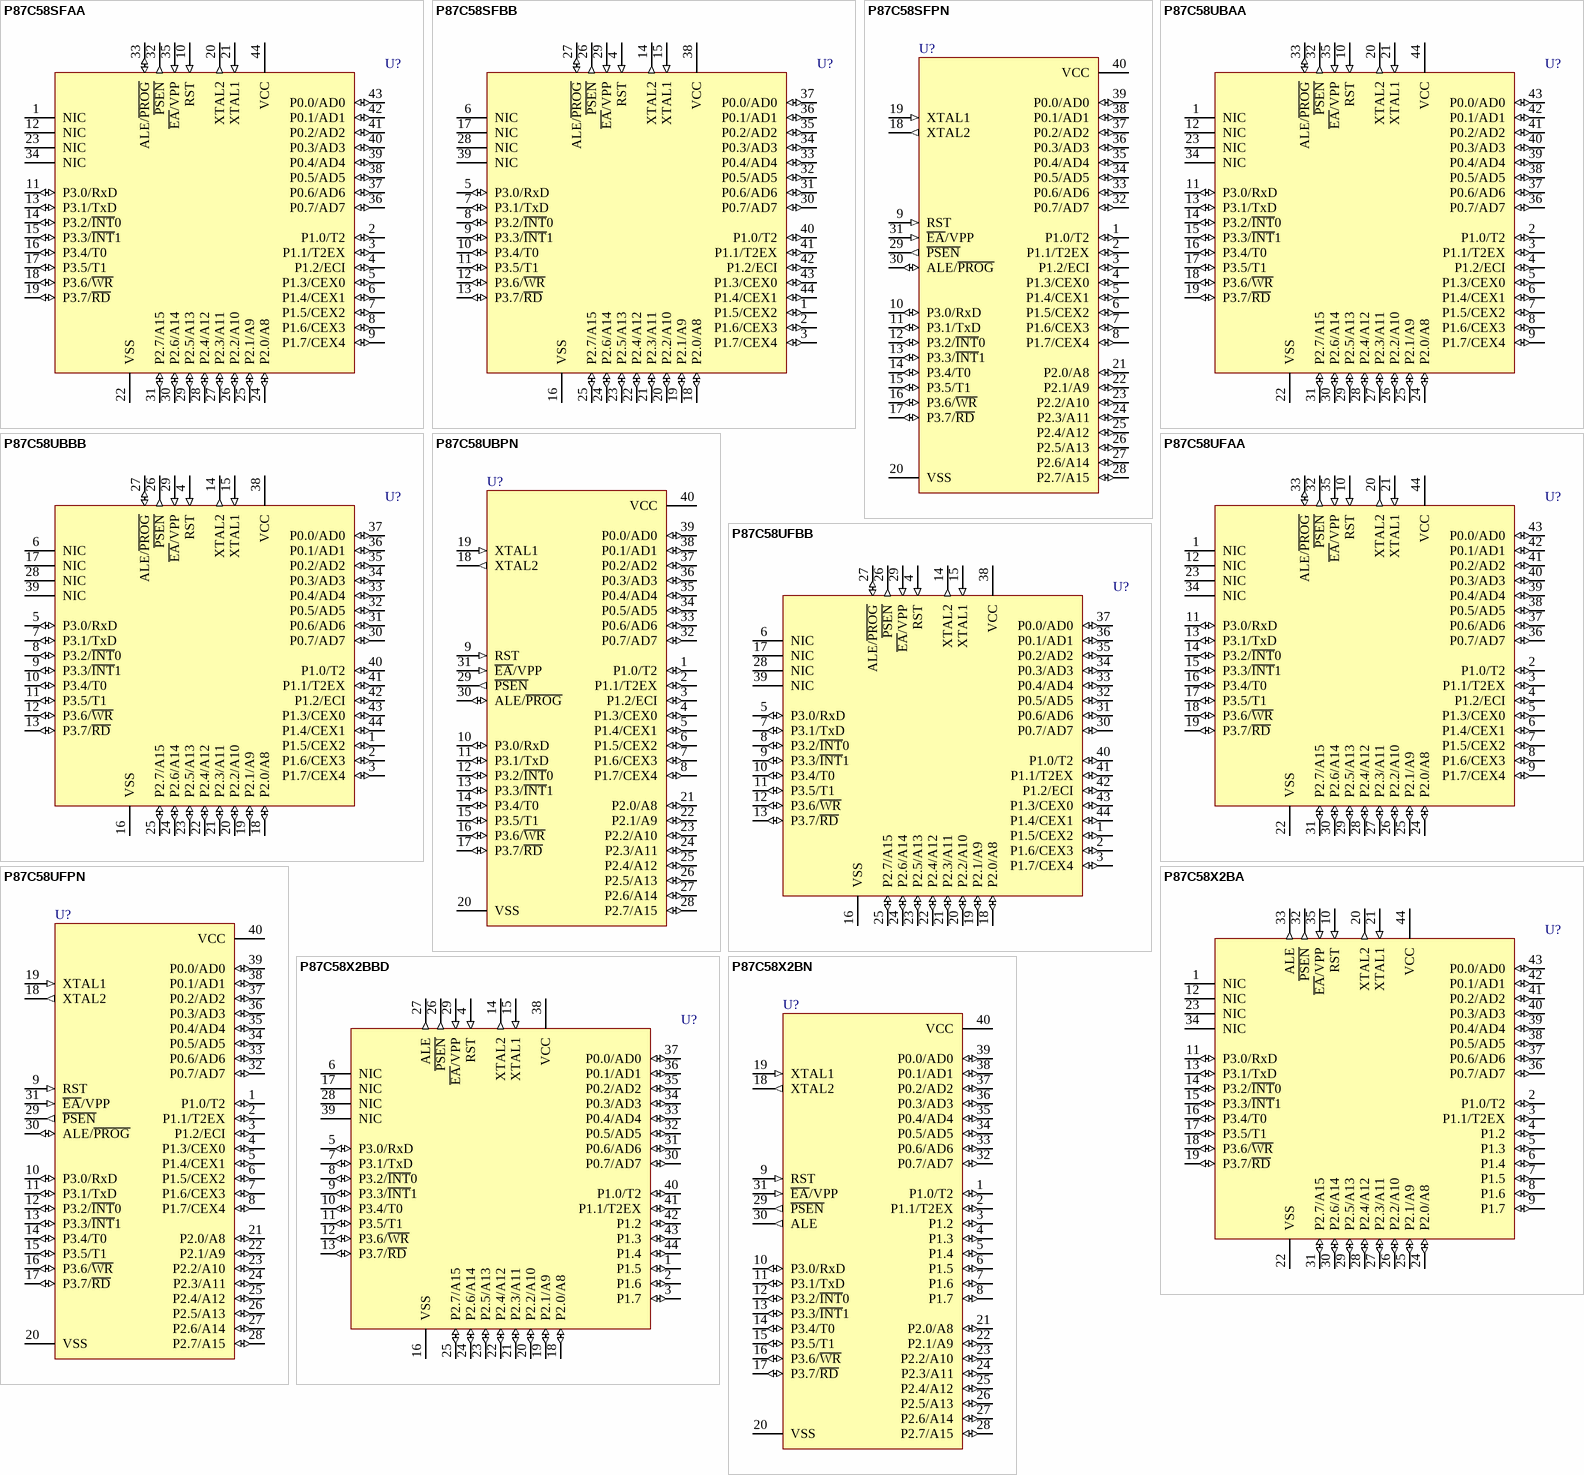
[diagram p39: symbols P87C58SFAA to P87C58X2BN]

## P87C58SFAA
designator U?
80C51 8-Bit Microcontroller Family: 256 B RAM, 32 kB OTP, 2.7V-5.5V, Low Power, High Speed
footprint SOT187-2_N (Leaded Chip Carrier, 44-Leads, Body 16.6x16.6mm, Pitch 1.27mm, IPC Medium Density)
footprint SOT187-2_L (Leaded Chip Carrier, 44-Leads, Body 16.6x16.6mm, Pitch 1.27mm, IPC High Density)
footprint SOT187-2_M (Leaded Chip Carrier, 44-Leads, Body 16.6x16.6mm, Pitch 1.27mm, IPC Low Density)
pins: 1 NIC, 2 P1.0/T2 (io), 3 P1.1/T2EX (io), 4 P1.2/ECI (io), 5 P1.3/CEX0 (io), 6 P1.4/CEX1 (io), 7 P1.5/CEX2 (io), 8 P1.6/CEX3 (io), 9 P1.7/CEX4 (io), 10 RST (in), 11 P3.0/RxD (io), 12 NIC, 13 P3.1/TxD (io), 14 P3.2/~{INT}0 (io), 15 P3.3/~{INT}1 (io), 16 P3.4/T0 (io), 17 P3.5/T1 (io), 18 P3.6/~{WR} (io), 19 P3.7/~{RD} (io), 20 XTAL2 (out), 21 XTAL1 (in), 22 VSS (power), 23 NIC, 24 P2.0/A8 (io), 25 P2.1/A9 (io), 26 P2.2/A10 (io), 27 P2.3/A11 (io), 28 P2.4/A12 (io), 29 P2.5/A13 (io), 30 P2.6/A14 (io), 31 P2.7/A15 (io), 32 ~{PSEN} (out), 33 ALE/~{PROG} (io), 34 NIC, 35 ~{EA}/VPP (in), 36 P0.7/AD7 (io), 37 P0.6/AD6 (io), 38 P0.5/AD5 (io), 39 P0.4/AD4 (io), 40 P0.3/AD3 (io), 41 P0.2/AD2 (io), 42 P0.1/AD1 (io), 43 P0.0/AD0 (io), 44 VCC (power)

## P87C58SFBB
designator U?
80C51 8-Bit Microcontroller Family: 256 B RAM, 32 kB OTP, 2.7V-5.5V, Low Power, High Speed
footprint SOT307-2_N (QFP, 44-Leads, Body 10x10mm, Pitch 0.8mm, IPC Medium Density)
footprint SOT307-2_L (QFP, 44-Leads, Body 10x10mm, Pitch 0.8mm, IPC High Density)
footprint SOT307-2_M (QFP, 44-Leads, Body 10x10mm, Pitch 0.8mm, IPC Low Density)
pins: 1 P1.5/CEX2 (io), 2 P1.6/CEX3 (io), 3 P1.7/CEX4 (io), 4 RST (in), 5 P3.0/RxD (io), 6 NIC, 7 P3.1/TxD (io), 8 P3.2/~{INT}0 (io), 9 P3.3/~{INT}1 (io), 10 P3.4/T0 (io), 11 P3.5/T1 (io), 12 P3.6/~{WR} (io), 13 P3.7/~{RD} (io), 14 XTAL2 (out), 15 XTAL1 (in), 16 VSS (power), 17 NIC, 18 P2.0/A8 (io), 19 P2.1/A9 (io), 20 P2.2/A10 (io), 21 P2.3/A11 (io), 22 P2.4/A12 (io), 23 P2.5/A13 (io), 24 P2.6/A14 (io), 25 P2.7/A15 (io), 26 ~{PSEN} (out), 27 ALE/~{PROG} (io), 28 NIC, 29 ~{EA}/VPP (in), 30 P0.7/AD7 (io), 31 P0.6/AD6 (io), 32 P0.5/AD5 (io), 33 P0.4/AD4 (io), 34 P0.3/AD3 (io), 35 P0.2/AD2 (io), 36 P0.1/AD1 (io), 37 P0.0/AD0 (io), 38 VCC (power), 39 NIC, 40 P1.0/T2 (io), 41 P1.1/T2EX (io), 42 P1.2/ECI (io), 43 P1.3/CEX0 (io), 44 P1.4/CEX1 (io)

## P87C58SFPN
designator U?
80C51 8-Bit Microcontroller Family: 256 B RAM, 32 kB OTP, 2.7V-5.5V, Low Power, High Speed
footprint SOT129-1 (DIP, Plastic; 40 Leads; Row Spacing 15.24 mm; Pitch 2.54 mm)
pins: 1 P1.0/T2 (io), 2 P1.1/T2EX (io), 3 P1.2/ECI (io), 4 P1.3/CEX0 (io), 5 P1.4/CEX1 (io), 6 P1.5/CEX2 (io), 7 P1.6/CEX3 (io), 8 P1.7/CEX4 (io), 9 RST (in), 10 P3.0/RxD (io), 11 P3.1/TxD (io), 12 P3.2/~{INT}0 (io), 13 P3.3/~{INT}1 (io), 14 P3.4/T0 (io), 15 P3.5/T1 (io), 16 P3.6/~{WR} (io), 17 P3.7/~{RD} (io), 18 XTAL2 (out), 19 XTAL1 (in), 20 VSS (power), 21 P2.0/A8 (io), 22 P2.1/A9 (io), 23 P2.2/A10 (io), 24 P2.3/A11 (io), 25 P2.4/A12 (io), 26 P2.5/A13 (io), 27 P2.6/A14 (io), 28 P2.7/A15 (io), 29 ~{PSEN} (out), 30 ALE/~{PROG} (io), 31 ~{EA}/VPP (in), 32 P0.7/AD7 (io), 33 P0.6/AD6 (io), 34 P0.5/AD5 (io), 35 P0.4/AD4 (io), 36 P0.3/AD3 (io), 37 P0.2/AD2 (io), 38 P0.1/AD1 (io), 39 P0.0/AD0 (io), 40 VCC (power)

## P87C58UBAA
designator U?
80C51 8-Bit Microcontroller Family: 256 B RAM, 32 kB OTP, 5V, Low Power, High Speed
footprint SOT187-2_N (Leaded Chip Carrier, 44-Leads, Body 16.6x16.6mm, Pitch 1.27mm, IPC Medium Density)
footprint SOT187-2_L (Leaded Chip Carrier, 44-Leads, Body 16.6x16.6mm, Pitch 1.27mm, IPC High Density)
footprint SOT187-2_M (Leaded Chip Carrier, 44-Leads, Body 16.6x16.6mm, Pitch 1.27mm, IPC Low Density)
pins: 1 NIC, 2 P1.0/T2 (io), 3 P1.1/T2EX (io), 4 P1.2/ECI (io), 5 P1.3/CEX0 (io), 6 P1.4/CEX1 (io), 7 P1.5/CEX2 (io), 8 P1.6/CEX3 (io), 9 P1.7/CEX4 (io), 10 RST (in), 11 P3.0/RxD (io), 12 NIC, 13 P3.1/TxD (io), 14 P3.2/~{INT}0 (io), 15 P3.3/~{INT}1 (io), 16 P3.4/T0 (io), 17 P3.5/T1 (io), 18 P3.6/~{WR} (io), 19 P3.7/~{RD} (io), 20 XTAL2 (out), 21 XTAL1 (in), 22 VSS (power), 23 NIC, 24 P2.0/A8 (io), 25 P2.1/A9 (io), 26 P2.2/A10 (io), 27 P2.3/A11 (io), 28 P2.4/A12 (io), 29 P2.5/A13 (io), 30 P2.6/A14 (io), 31 P2.7/A15 (io), 32 ~{PSEN} (out), 33 ALE/~{PROG} (io), 34 NIC, 35 ~{EA}/VPP (in), 36 P0.7/AD7 (io), 37 P0.6/AD6 (io), 38 P0.5/AD5 (io), 39 P0.4/AD4 (io), 40 P0.3/AD3 (io), 41 P0.2/AD2 (io), 42 P0.1/AD1 (io), 43 P0.0/AD0 (io), 44 VCC (power)

## P87C58UBBB
designator U?
80C51 8-Bit Microcontroller Family: 256 B RAM, 32 kB OTP, 5V, Low Power, High Speed
footprint SOT307-2_N (QFP, 44-Leads, Body 10x10mm, Pitch 0.8mm, IPC Medium Density)
footprint SOT307-2_L (QFP, 44-Leads, Body 10x10mm, Pitch 0.8mm, IPC High Density)
footprint SOT307-2_M (QFP, 44-Leads, Body 10x10mm, Pitch 0.8mm, IPC Low Density)
pins: 1 P1.5/CEX2 (io), 2 P1.6/CEX3 (io), 3 P1.7/CEX4 (io), 4 RST (in), 5 P3.0/RxD (io), 6 NIC, 7 P3.1/TxD (io), 8 P3.2/~{INT}0 (io), 9 P3.3/~{INT}1 (io), 10 P3.4/T0 (io), 11 P3.5/T1 (io), 12 P3.6/~{WR} (io), 13 P3.7/~{RD} (io), 14 XTAL2 (out), 15 XTAL1 (in), 16 VSS (power), 17 NIC, 18 P2.0/A8 (io), 19 P2.1/A9 (io), 20 P2.2/A10 (io), 21 P2.3/A11 (io), 22 P2.4/A12 (io), 23 P2.5/A13 (io), 24 P2.6/A14 (io), 25 P2.7/A15 (io), 26 ~{PSEN} (out), 27 ALE/~{PROG} (io), 28 NIC, 29 ~{EA}/VPP (in), 30 P0.7/AD7 (io), 31 P0.6/AD6 (io), 32 P0.5/AD5 (io), 33 P0.4/AD4 (io), 34 P0.3/AD3 (io), 35 P0.2/AD2 (io), 36 P0.1/AD1 (io), 37 P0.0/AD0 (io), 38 VCC (power), 39 NIC, 40 P1.0/T2 (io), 41 P1.1/T2EX (io), 42 P1.2/ECI (io), 43 P1.3/CEX0 (io), 44 P1.4/CEX1 (io)

## P87C58UBPN
designator U?
80C51 8-Bit Microcontroller Family: 256 B RAM, 32 kB OTP, 5V, Low Power, High Speed
footprint SOT129-1 (DIP, Plastic; 40 Leads; Row Spacing 15.24 mm; Pitch 2.54 mm)
pins: 1 P1.0/T2 (io), 2 P1.1/T2EX (io), 3 P1.2/ECI (io), 4 P1.3/CEX0 (io), 5 P1.4/CEX1 (io), 6 P1.5/CEX2 (io), 7 P1.6/CEX3 (io), 8 P1.7/CEX4 (io), 9 RST (in), 10 P3.0/RxD (io), 11 P3.1/TxD (io), 12 P3.2/~{INT}0 (io), 13 P3.3/~{INT}1 (io), 14 P3.4/T0 (io), 15 P3.5/T1 (io), 16 P3.6/~{WR} (io), 17 P3.7/~{RD} (io), 18 XTAL2 (out), 19 XTAL1 (in), 20 VSS (power), 21 P2.0/A8 (io), 22 P2.1/A9 (io), 23 P2.2/A10 (io), 24 P2.3/A11 (io), 25 P2.4/A12 (io), 26 P2.5/A13 (io), 27 P2.6/A14 (io), 28 P2.7/A15 (io), 29 ~{PSEN} (out), 30 ALE/~{PROG} (io), 31 ~{EA}/VPP (in), 32 P0.7/AD7 (io), 33 P0.6/AD6 (io), 34 P0.5/AD5 (io), 35 P0.4/AD4 (io), 36 P0.3/AD3 (io), 37 P0.2/AD2 (io), 38 P0.1/AD1 (io), 39 P0.0/AD0 (io), 40 VCC (power)

## P87C58UFAA
designator U?
80C51 8-Bit Microcontroller Family: 256 B RAM, 32 kB OTP, 5V, Low Power, High Speed
footprint SOT187-2_N (Leaded Chip Carrier, 44-Leads, Body 16.6x16.6mm, Pitch 1.27mm, IPC Medium Density)
footprint SOT187-2_L (Leaded Chip Carrier, 44-Leads, Body 16.6x16.6mm, Pitch 1.27mm, IPC High Density)
footprint SOT187-2_M (Leaded Chip Carrier, 44-Leads, Body 16.6x16.6mm, Pitch 1.27mm, IPC Low Density)
pins: 1 NIC, 2 P1.0/T2 (io), 3 P1.1/T2EX (io), 4 P1.2/ECI (io), 5 P1.3/CEX0 (io), 6 P1.4/CEX1 (io), 7 P1.5/CEX2 (io), 8 P1.6/CEX3 (io), 9 P1.7/CEX4 (io), 10 RST (in), 11 P3.0/RxD (io), 12 NIC, 13 P3.1/TxD (io), 14 P3.2/~{INT}0 (io), 15 P3.3/~{INT}1 (io), 16 P3.4/T0 (io), 17 P3.5/T1 (io), 18 P3.6/~{WR} (io), 19 P3.7/~{RD} (io), 20 XTAL2 (out), 21 XTAL1 (in), 22 VSS (power), 23 NIC, 24 P2.0/A8 (io), 25 P2.1/A9 (io), 26 P2.2/A10 (io), 27 P2.3/A11 (io), 28 P2.4/A12 (io), 29 P2.5/A13 (io), 30 P2.6/A14 (io), 31 P2.7/A15 (io), 32 ~{PSEN} (out), 33 ALE/~{PROG} (io), 34 NIC, 35 ~{EA}/VPP (in), 36 P0.7/AD7 (io), 37 P0.6/AD6 (io), 38 P0.5/AD5 (io), 39 P0.4/AD4 (io), 40 P0.3/AD3 (io), 41 P0.2/AD2 (io), 42 P0.1/AD1 (io), 43 P0.0/AD0 (io), 44 VCC (power)

## P87C58UFBB
designator U?
80C51 8-Bit Microcontroller Family: 256 B RAM, 32 kB OTP, 5V, Low Power, High Speed
footprint SOT307-2_N (QFP, 44-Leads, Body 10x10mm, Pitch 0.8mm, IPC Medium Density)
footprint SOT307-2_L (QFP, 44-Leads, Body 10x10mm, Pitch 0.8mm, IPC High Density)
footprint SOT307-2_M (QFP, 44-Leads, Body 10x10mm, Pitch 0.8mm, IPC Low Density)
pins: 1 P1.5/CEX2 (io), 2 P1.6/CEX3 (io), 3 P1.7/CEX4 (io), 4 RST (in), 5 P3.0/RxD (io), 6 NIC, 7 P3.1/TxD (io), 8 P3.2/~{INT}0 (io), 9 P3.3/~{INT}1 (io), 10 P3.4/T0 (io), 11 P3.5/T1 (io), 12 P3.6/~{WR} (io), 13 P3.7/~{RD} (io), 14 XTAL2 (out), 15 XTAL1 (in), 16 VSS (power), 17 NIC, 18 P2.0/A8 (io), 19 P2.1/A9 (io), 20 P2.2/A10 (io), 21 P2.3/A11 (io), 22 P2.4/A12 (io), 23 P2.5/A13 (io), 24 P2.6/A14 (io), 25 P2.7/A15 (io), 26 ~{PSEN} (out), 27 ALE/~{PROG} (io), 28 NIC, 29 ~{EA}/VPP (in), 30 P0.7/AD7 (io), 31 P0.6/AD6 (io), 32 P0.5/AD5 (io), 33 P0.4/AD4 (io), 34 P0.3/AD3 (io), 35 P0.2/AD2 (io), 36 P0.1/AD1 (io), 37 P0.0/AD0 (io), 38 VCC (power), 39 NIC, 40 P1.0/T2 (io), 41 P1.1/T2EX (io), 42 P1.2/ECI (io), 43 P1.3/CEX0 (io), 44 P1.4/CEX1 (io)

## P87C58UFPN
designator U?
80C51 8-Bit Microcontroller Family: 256 B RAM, 32 kB OTP, 5V, Low Power, High Speed
footprint SOT129-1 (DIP, Plastic; 40 Leads; Row Spacing 15.24 mm; Pitch 2.54 mm)
pins: 1 P1.0/T2 (io), 2 P1.1/T2EX (io), 3 P1.2/ECI (io), 4 P1.3/CEX0 (io), 5 P1.4/CEX1 (io), 6 P1.5/CEX2 (io), 7 P1.6/CEX3 (io), 8 P1.7/CEX4 (io), 9 RST (in), 10 P3.0/RxD (io), 11 P3.1/TxD (io), 12 P3.2/~{INT}0 (io), 13 P3.3/~{INT}1 (io), 14 P3.4/T0 (io), 15 P3.5/T1 (io), 16 P3.6/~{WR} (io), 17 P3.7/~{RD} (io), 18 XTAL2 (out), 19 XTAL1 (in), 20 VSS (power), 21 P2.0/A8 (io), 22 P2.1/A9 (io), 23 P2.2/A10 (io), 24 P2.3/A11 (io), 25 P2.4/A12 (io), 26 P2.5/A13 (io), 27 P2.6/A14 (io), 28 P2.7/A15 (io), 29 ~{PSEN} (out), 30 ALE/~{PROG} (io), 31 ~{EA}/VPP (in), 32 P0.7/AD7 (io), 33 P0.6/AD6 (io), 34 P0.5/AD5 (io), 35 P0.4/AD4 (io), 36 P0.3/AD3 (io), 37 P0.2/AD2 (io), 38 P0.1/AD1 (io), 39 P0.0/AD0 (io), 40 VCC (power)

## P87C58X2BA
designator U?
80C51 8-Bit Microcontroller Family: 256 B RAM, 32 kB OTP, 2.7 to 5.5 V, Low Power, High Speed
footprint SOT187-2_N (Leaded Chip Carrier, 44-Leads, Body 16.6x16.6mm, Pitch 1.27mm, IPC Medium Density)
footprint SOT187-2_L (Leaded Chip Carrier, 44-Leads, Body 16.6x16.6mm, Pitch 1.27mm, IPC High Density)
footprint SOT187-2_M (Leaded Chip Carrier, 44-Leads, Body 16.6x16.6mm, Pitch 1.27mm, IPC Low Density)
pins: 1 NIC, 2 P1.0/T2 (io), 3 P1.1/T2EX (io), 4 P1.2 (io), 5 P1.3 (io), 6 P1.4 (io), 7 P1.5 (io), 8 P1.6 (io), 9 P1.7 (io), 10 RST (in), 11 P3.0/RxD (io), 12 NIC, 13 P3.1/TxD (io), 14 P3.2/~{INT}0 (io), 15 P3.3/~{INT}1 (io), 16 P3.4/T0 (io), 17 P3.5/T1 (io), 18 P3.6/~{WR} (io), 19 P3.7/~{RD} (io), 20 XTAL2 (out), 21 XTAL1 (in), 22 VSS (power), 23 NIC, 24 P2.0/A8 (io), 25 P2.1/A9 (io), 26 P2.2/A10 (io), 27 P2.3/A11 (io), 28 P2.4/A12 (io), 29 P2.5/A13 (io), 30 P2.6/A14 (io), 31 P2.7/A15 (io), 32 ~{PSEN} (out), 33 ALE (out), 34 NIC, 35 ~{EA}/VPP (in), 36 P0.7/AD7 (io), 37 P0.6/AD6 (io), 38 P0.5/AD5 (io), 39 P0.4/AD4 (io), 40 P0.3/AD3 (io), 41 P0.2/AD2 (io), 42 P0.1/AD1 (io), 43 P0.0/AD0 (io), 44 VCC (power)

## P87C58X2BBD
designator U?
80C51 8-Bit Microcontroller Family: 256 B RAM, 32 kB OTP, 2.7 to 5.5 V, Low Power, High Speed
footprint SOT389-1_N (Thin QFP, 44-Leads, Body 10x10mm, Pitch 0.8mm, IPC Medium Density)
footprint SOT389-1_L (Thin QFP, 44-Leads, Body 10x10mm, Pitch 0.8mm, IPC High Density)
footprint SOT389-1_M (Thin QFP, 44-Leads, Body 10x10mm, Pitch 0.8mm, IPC Low Density)
pins: 1 P1.5 (io), 2 P1.6 (io), 3 P1.7 (io), 4 RST (in), 5 P3.0/RxD (io), 6 NIC, 7 P3.1/TxD (io), 8 P3.2/~{INT}0 (io), 9 P3.3/~{INT}1 (io), 10 P3.4/T0 (io), 11 P3.5/T1 (io), 12 P3.6/~{WR} (io), 13 P3.7/~{RD} (io), 14 XTAL2 (out), 15 XTAL1 (in), 16 VSS (power), 17 NIC, 18 P2.0/A8 (io), 19 P2.1/A9 (io), 20 P2.2/A10 (io), 21 P2.3/A11 (io), 22 P2.4/A12 (io), 23 P2.5/A13 (io), 24 P2.6/A14 (io), 25 P2.7/A15 (io), 26 ~{PSEN} (out), 27 ALE (out), 28 NIC, 29 ~{EA}/VPP (in), 30 P0.7/AD7 (io), 31 P0.6/AD6 (io), 32 P0.5/AD5 (io), 33 P0.4/AD4 (io), 34 P0.3/AD3 (io), 35 P0.2/AD2 (io), 36 P0.1/AD1 (io), 37 P0.0/AD0 (io), 38 VCC (power), 39 NIC, 40 P1.0/T2 (io), 41 P1.1/T2EX (io), 42 P1.2 (io), 43 P1.3 (io), 44 P1.4 (io)

## P87C58X2BN
designator U?
80C51 8-Bit Microcontroller Family: 256 B RAM, 32 kB OTP, 2.7 to 5.5 V, Low Power, High Speed
footprint SOT129-1 (DIP, Plastic; 40 Leads; Row Spacing 15.24 mm; Pitch 2.54 mm)
pins: 1 P1.0/T2 (io), 2 P1.1/T2EX (io), 3 P1.2 (io), 4 P1.3 (io), 5 P1.4 (io), 6 P1.5 (io), 7 P1.6 (io), 8 P1.7 (io), 9 RST (in), 10 P3.0/RxD (io), 11 P3.1/TxD (io), 12 P3.2/~{INT}0 (io), 13 P3.3/~{INT}1 (io), 14 P3.4/T0 (io), 15 P3.5/T1 (io), 16 P3.6/~{WR} (io), 17 P3.7/~{RD} (io), 18 XTAL2 (out), 19 XTAL1 (in), 20 VSS (power), 21 P2.0/A8 (io), 22 P2.1/A9 (io), 23 P2.2/A10 (io), 24 P2.3/A11 (io), 25 P2.4/A12 (io), 26 P2.5/A13 (io), 27 P2.6/A14 (io), 28 P2.7/A15 (io), 29 ~{PSEN} (out), 30 ALE (out), 31 ~{EA}/VPP (in), 32 P0.7/AD7 (io), 33 P0.6/AD6 (io), 34 P0.5/AD5 (io), 35 P0.4/AD4 (io), 36 P0.3/AD3 (io), 37 P0.2/AD2 (io), 38 P0.1/AD1 (io), 39 P0.0/AD0 (io), 40 VCC (power)

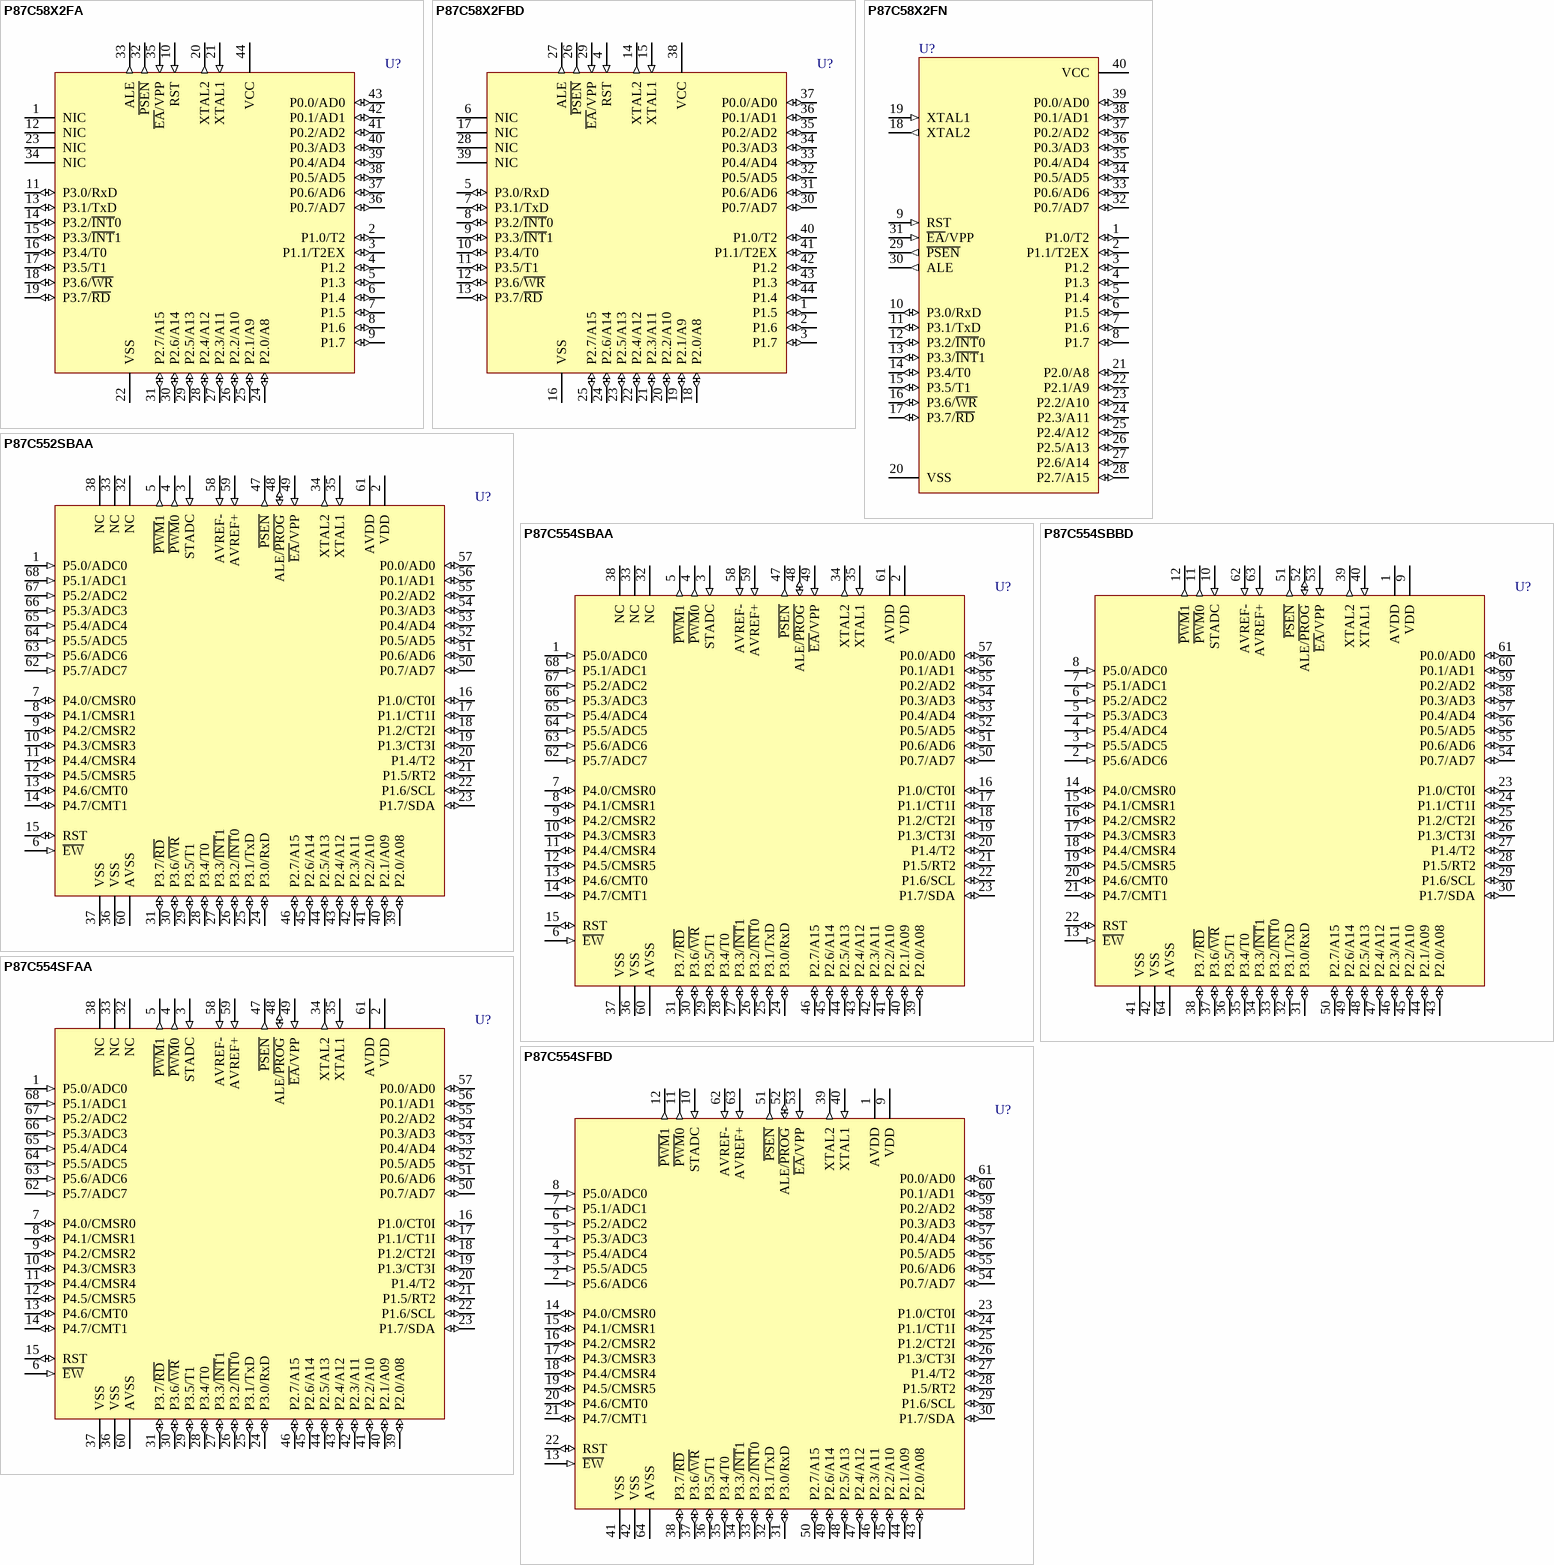
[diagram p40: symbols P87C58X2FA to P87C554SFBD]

## P87C58X2FA
designator U?
80C51 8-Bit Microcontroller Family: 256 B RAM, 32 kB OTP, 2.7 to 5.5 V, Low Power, High Speed
footprint SOT187-2_N (Leaded Chip Carrier, 44-Leads, Body 16.6x16.6mm, Pitch 1.27mm, IPC Medium Density)
footprint SOT187-2_L (Leaded Chip Carrier, 44-Leads, Body 16.6x16.6mm, Pitch 1.27mm, IPC High Density)
footprint SOT187-2_M (Leaded Chip Carrier, 44-Leads, Body 16.6x16.6mm, Pitch 1.27mm, IPC Low Density)
pins: 1 NIC, 2 P1.0/T2 (io), 3 P1.1/T2EX (io), 4 P1.2 (io), 5 P1.3 (io), 6 P1.4 (io), 7 P1.5 (io), 8 P1.6 (io), 9 P1.7 (io), 10 RST (in), 11 P3.0/RxD (io), 12 NIC, 13 P3.1/TxD (io), 14 P3.2/~{INT}0 (io), 15 P3.3/~{INT}1 (io), 16 P3.4/T0 (io), 17 P3.5/T1 (io), 18 P3.6/~{WR} (io), 19 P3.7/~{RD} (io), 20 XTAL2 (out), 21 XTAL1 (in), 22 VSS (power), 23 NIC, 24 P2.0/A8 (io), 25 P2.1/A9 (io), 26 P2.2/A10 (io), 27 P2.3/A11 (io), 28 P2.4/A12 (io), 29 P2.5/A13 (io), 30 P2.6/A14 (io), 31 P2.7/A15 (io), 32 ~{PSEN} (out), 33 ALE (out), 34 NIC, 35 ~{EA}/VPP (in), 36 P0.7/AD7 (io), 37 P0.6/AD6 (io), 38 P0.5/AD5 (io), 39 P0.4/AD4 (io), 40 P0.3/AD3 (io), 41 P0.2/AD2 (io), 42 P0.1/AD1 (io), 43 P0.0/AD0 (io), 44 VCC (power)

## P87C58X2FBD
designator U?
80C51 8-Bit Microcontroller Family: 256 B RAM, 32 kB OTP, 2.7 to 5.5 V, Low Power, High Speed
footprint SOT389-1_N (Thin QFP, 44-Leads, Body 10x10mm, Pitch 0.8mm, IPC Medium Density)
footprint SOT389-1_L (Thin QFP, 44-Leads, Body 10x10mm, Pitch 0.8mm, IPC High Density)
footprint SOT389-1_M (Thin QFP, 44-Leads, Body 10x10mm, Pitch 0.8mm, IPC Low Density)
pins: 1 P1.5 (io), 2 P1.6 (io), 3 P1.7 (io), 4 RST (in), 5 P3.0/RxD (io), 6 NIC, 7 P3.1/TxD (io), 8 P3.2/~{INT}0 (io), 9 P3.3/~{INT}1 (io), 10 P3.4/T0 (io), 11 P3.5/T1 (io), 12 P3.6/~{WR} (io), 13 P3.7/~{RD} (io), 14 XTAL2 (out), 15 XTAL1 (in), 16 VSS (power), 17 NIC, 18 P2.0/A8 (io), 19 P2.1/A9 (io), 20 P2.2/A10 (io), 21 P2.3/A11 (io), 22 P2.4/A12 (io), 23 P2.5/A13 (io), 24 P2.6/A14 (io), 25 P2.7/A15 (io), 26 ~{PSEN} (out), 27 ALE (out), 28 NIC, 29 ~{EA}/VPP (in), 30 P0.7/AD7 (io), 31 P0.6/AD6 (io), 32 P0.5/AD5 (io), 33 P0.4/AD4 (io), 34 P0.3/AD3 (io), 35 P0.2/AD2 (io), 36 P0.1/AD1 (io), 37 P0.0/AD0 (io), 38 VCC (power), 39 NIC, 40 P1.0/T2 (io), 41 P1.1/T2EX (io), 42 P1.2 (io), 43 P1.3 (io), 44 P1.4 (io)

## P87C58X2FN
designator U?
80C51 8-Bit Microcontroller Family: 256 B RAM, 32 kB OTP, 2.7 to 5.5 V, Low Power, High Speed
footprint SOT129-1 (DIP, Plastic; 40 Leads; Row Spacing 15.24 mm; Pitch 2.54 mm)
pins: 1 P1.0/T2 (io), 2 P1.1/T2EX (io), 3 P1.2 (io), 4 P1.3 (io), 5 P1.4 (io), 6 P1.5 (io), 7 P1.6 (io), 8 P1.7 (io), 9 RST (in), 10 P3.0/RxD (io), 11 P3.1/TxD (io), 12 P3.2/~{INT}0 (io), 13 P3.3/~{INT}1 (io), 14 P3.4/T0 (io), 15 P3.5/T1 (io), 16 P3.6/~{WR} (io), 17 P3.7/~{RD} (io), 18 XTAL2 (out), 19 XTAL1 (in), 20 VSS (power), 21 P2.0/A8 (io), 22 P2.1/A9 (io), 23 P2.2/A10 (io), 24 P2.3/A11 (io), 25 P2.4/A12 (io), 26 P2.5/A13 (io), 27 P2.6/A14 (io), 28 P2.7/A15 (io), 29 ~{PSEN} (out), 30 ALE (out), 31 ~{EA}/VPP (in), 32 P0.7/AD7 (io), 33 P0.6/AD6 (io), 34 P0.5/AD5 (io), 35 P0.4/AD4 (io), 36 P0.3/AD3 (io), 37 P0.2/AD2 (io), 38 P0.1/AD1 (io), 39 P0.0/AD0 (io), 40 VCC (power)

## P87C552SBAA
designator U?
80C51 8-Bit Microcontroller, 8K/256 OTP, 8-Channel 10-bit A/D, I²C, PWM, Capture/Compare, High I/O, 2.7V-5.5V, Low Power
footprint SOT188-3_N (Leaded Chip Carrier, 68-Leads, Body 24.2x24.2mm, Pitch 1.27mm, IPC Medium Density)
footprint SOT188-3_L (Leaded Chip Carrier, 68-Leads, Body 24.2x24.2mm, Pitch 1.27mm, IPC High Density)
footprint SOT188-3_M (Leaded Chip Carrier, 68-Leads, Body 24.2x24.2mm, Pitch 1.27mm, IPC Low Density)
pins: 1 P5.0/ADC0 (in), 2 VDD (power), 3 STADC (in), 4 ~{PWM}0 (out), 5 ~{PWM}1 (out), 6 ~{EW} (in), 7 P4.0/CMSR0 (io), 8 P4.1/CMSR1 (io), 9 P4.2/CMSR2 (io), 10 P4.3/CMSR3 (io), 11 P4.4/CMSR4 (io), 12 P4.5/CMSR5 (io), 13 P4.6/CMT0 (io), 14 P4.7/CMT1 (io), 15 RST (io), 16 P1.0/CT0I (io), 17 P1.1/CT1I (io), 18 P1.2/CT2I (io), 19 P1.3/CT3I (io), 20 P1.4/T2 (io), 21 P1.5/RT2 (io), 22 P1.6/SCL (io), 23 P1.7/SDA (io), 24 P3.0/RxD (io), 25 P3.1/TxD (io), 26 P3.2/~{INT}0 (io), 27 P3.3/~{INT}1 (io), 28 P3.4/T0 (io), 29 P3.5/T1 (io), 30 P3.6/~{WR} (io), 31 P3.7/~{RD} (io), 32 NC, 33 NC, 34 XTAL2 (out), 35 XTAL1 (in), 36 VSS (power), 37 VSS (power), 38 NC, 39 P2.0/A08 (io), 40 P2.1/A09 (io), 41 P2.2/A10 (io), 42 P2.3/A11 (io), 43 P2.4/A12 (io), 44 P2.5/A13 (io), 45 P2.6/A14 (io), 46 P2.7/A15 (io), 47 ~{PSEN} (out), 48 ALE/~{PROG} (io), 49 ~{EA}/VPP (in), 50 P0.7/AD7 (io), 51 P0.6/AD6 (io), 52 P0.5/AD5 (io), 53 P0.4/AD4 (io), 54 P0.3/AD3 (io), 55 P0.2/AD2 (io), 56 P0.1/AD1 (io), 57 P0.0/AD0 (io), 58 AVREF- (in), 59 AVREF+ (in), 60 AVSS (power), 61 AVDD (power), 62 P5.7/ADC7 (in), 63 P5.6/ADC6 (in), 64 P5.5/ADC5 (in), 65 P5.4/ADC4 (in), 66 P5.3/ADC3 (in), 67 P5.2/ADC2 (in), 68 P5.1/ADC1 (in)

## P87C554SBAA
designator U?
80C51 8-Bit Microcontroller - 12 Clock Operation, 16K/512 OTP/RAM, 8-Channel 10-bit A/D, I²C, PWM, Capture/Compare, High I/O
footprint SOT188-3_N (Leaded Chip Carrier, 68-Leads, Body 24.2x24.2mm, Pitch 1.27mm, IPC Medium Density)
footprint SOT188-3_L (Leaded Chip Carrier, 68-Leads, Body 24.2x24.2mm, Pitch 1.27mm, IPC High Density)
footprint SOT188-3_M (Leaded Chip Carrier, 68-Leads, Body 24.2x24.2mm, Pitch 1.27mm, IPC Low Density)
pins: 1 P5.0/ADC0 (in), 2 VDD (power), 3 STADC (in), 4 ~{PWM}0 (out), 5 ~{PWM}1 (out), 6 ~{EW} (in), 7 P4.0/CMSR0 (io), 8 P4.1/CMSR1 (io), 9 P4.2/CMSR2 (io), 10 P4.3/CMSR3 (io), 11 P4.4/CMSR4 (io), 12 P4.5/CMSR5 (io), 13 P4.6/CMT0 (io), 14 P4.7/CMT1 (io), 15 RST (io), 16 P1.0/CT0I (io), 17 P1.1/CT1I (io), 18 P1.2/CT2I (io), 19 P1.3/CT3I (io), 20 P1.4/T2 (io), 21 P1.5/RT2 (io), 22 P1.6/SCL (io), 23 P1.7/SDA (io), 24 P3.0/RxD (io), 25 P3.1/TxD (io), 26 P3.2/~{INT}0 (io), 27 P3.3/~{INT}1 (io), 28 P3.4/T0 (io), 29 P3.5/T1 (io), 30 P3.6/~{WR} (io), 31 P3.7/~{RD} (io), 32 NC, 33 NC, 34 XTAL2 (out), 35 XTAL1 (in), 36 VSS (power), 37 VSS (power), 38 NC, 39 P2.0/A08 (io), 40 P2.1/A09 (io), 41 P2.2/A10 (io), 42 P2.3/A11 (io), 43 P2.4/A12 (io), 44 P2.5/A13 (io), 45 P2.6/A14 (io), 46 P2.7/A15 (io), 47 ~{PSEN} (out), 48 ALE/~{PROG} (io), 49 ~{EA}/VPP (in), 50 P0.7/AD7 (io), 51 P0.6/AD6 (io), 52 P0.5/AD5 (io), 53 P0.4/AD4 (io), 54 P0.3/AD3 (io), 55 P0.2/AD2 (io), 56 P0.1/AD1 (io), 57 P0.0/AD0 (io), 58 AVREF- (in), 59 AVREF+ (in), 60 AVSS (power), 61 AVDD (power), 62 P5.7/ADC7 (in), 63 P5.6/ADC6 (in), 64 P5.5/ADC5 (in), 65 P5.4/ADC4 (in), 66 P5.3/ADC3 (in), 67 P5.2/ADC2 (in), 68 P5.1/ADC1 (in)

## P87C554SBBD
designator U?
80C51 8-Bit Microcontroller - 6-Clock Operation, 16K/512 OTP, 7-channel 10-bit A/D, I²C, PWM, Capture/Compare, High I/O
footprint SOT314-2_N (Thin QFP, 64-Leads, Body 10x10mm, Pitch 0.5mm, IPC Medium Density)
footprint SOT314-2_L (Thin QFP, 64-Leads, Body 10x10mm, Pitch 0.5mm, IPC High Density)
footprint SOT314-2_M (Thin QFP, 64-Leads, Body 10x10mm, Pitch 0.5mm, IPC Low Density)
pins: 1 AVDD (power), 2 P5.6/ADC6 (in), 3 P5.5/ADC5 (in), 4 P5.4/ADC4 (in), 5 P5.3/ADC3 (in), 6 P5.2/ADC2 (in), 7 P5.1/ADC1 (in), 8 P5.0/ADC0 (in), 9 VDD (power), 10 STADC (in), 11 ~{PWM}0 (out), 12 ~{PWM}1 (out), 13 ~{EW} (in), 14 P4.0/CMSR0 (io), 15 P4.1/CMSR1 (io), 16 P4.2/CMSR2 (io), 17 P4.3/CMSR3 (io), 18 P4.4/CMSR4 (io), 19 P4.5/CMSR5 (io), 20 P4.6/CMT0 (io), 21 P4.7/CMT1 (io), 22 RST (io), 23 P1.0/CT0I (io), 24 P1.1/CT1I (io), 25 P1.2/CT2I (io), 26 P1.3/CT3I (io), 27 P1.4/T2 (io), 28 P1.5/RT2 (io), 29 P1.6/SCL (io), 30 P1.7/SDA (io), 31 P3.0/RxD (io), 32 P3.1/TxD (io), 33 P3.2/~{INT}0 (io), 34 P3.3/~{INT}1 (io), 35 P3.4/T0 (io), 36 P3.5/T1 (io), 37 P3.6/~{WR} (io), 38 P3.7/~{RD} (io), 39 XTAL2 (out), 40 XTAL1 (in), 41 VSS (power), 42 VSS (power), 43 P2.0/A08 (io), 44 P2.1/A09 (io), 45 P2.2/A10 (io), 46 P2.3/A11 (io), 47 P2.4/A12 (io), 48 P2.5/A13 (io), 49 P2.6/A14 (io), 50 P2.7/A15 (io), 51 ~{PSEN} (out), 52 ALE/~{PROG} (io), 53 ~{EA}/VPP (in), 54 P0.7/AD7 (io), 55 P0.6/AD6 (io), 56 P0.5/AD5 (io), 57 P0.4/AD4 (io), 58 P0.3/AD3 (io), 59 P0.2/AD2 (io), 60 P0.1/AD1 (io), 61 P0.0/AD0 (io), 62 AVREF- (in), 63 AVREF+ (in), 64 AVSS (power)

## P87C554SFAA
designator U?
80C51 8-Bit Microcontroller - 12 Clock Operation, 16K/512 OTP/RAM, 8-Channel 10-bit A/D, I²C, PWM, Capture/Compare, High I/O
footprint SOT188-3_N (Leaded Chip Carrier, 68-Leads, Body 24.2x24.2mm, Pitch 1.27mm, IPC Medium Density)
footprint SOT188-3_L (Leaded Chip Carrier, 68-Leads, Body 24.2x24.2mm, Pitch 1.27mm, IPC High Density)
footprint SOT188-3_M (Leaded Chip Carrier, 68-Leads, Body 24.2x24.2mm, Pitch 1.27mm, IPC Low Density)
pins: 1 P5.0/ADC0 (in), 2 VDD (power), 3 STADC (in), 4 ~{PWM}0 (out), 5 ~{PWM}1 (out), 6 ~{EW} (in), 7 P4.0/CMSR0 (io), 8 P4.1/CMSR1 (io), 9 P4.2/CMSR2 (io), 10 P4.3/CMSR3 (io), 11 P4.4/CMSR4 (io), 12 P4.5/CMSR5 (io), 13 P4.6/CMT0 (io), 14 P4.7/CMT1 (io), 15 RST (io), 16 P1.0/CT0I (io), 17 P1.1/CT1I (io), 18 P1.2/CT2I (io), 19 P1.3/CT3I (io), 20 P1.4/T2 (io), 21 P1.5/RT2 (io), 22 P1.6/SCL (io), 23 P1.7/SDA (io), 24 P3.0/RxD (io), 25 P3.1/TxD (io), 26 P3.2/~{INT}0 (io), 27 P3.3/~{INT}1 (io), 28 P3.4/T0 (io), 29 P3.5/T1 (io), 30 P3.6/~{WR} (io), 31 P3.7/~{RD} (io), 32 NC, 33 NC, 34 XTAL2 (out), 35 XTAL1 (in), 36 VSS (power), 37 VSS (power), 38 NC, 39 P2.0/A08 (io), 40 P2.1/A09 (io), 41 P2.2/A10 (io), 42 P2.3/A11 (io), 43 P2.4/A12 (io), 44 P2.5/A13 (io), 45 P2.6/A14 (io), 46 P2.7/A15 (io), 47 ~{PSEN} (out), 48 ALE/~{PROG} (io), 49 ~{EA}/VPP (in), 50 P0.7/AD7 (io), 51 P0.6/AD6 (io), 52 P0.5/AD5 (io), 53 P0.4/AD4 (io), 54 P0.3/AD3 (io), 55 P0.2/AD2 (io), 56 P0.1/AD1 (io), 57 P0.0/AD0 (io), 58 AVREF- (in), 59 AVREF+ (in), 60 AVSS (power), 61 AVDD (power), 62 P5.7/ADC7 (in), 63 P5.6/ADC6 (in), 64 P5.5/ADC5 (in), 65 P5.4/ADC4 (in), 66 P5.3/ADC3 (in), 67 P5.2/ADC2 (in), 68 P5.1/ADC1 (in)

## P87C554SFBD
designator U?
80C51 8-Bit Microcontroller - 6-Clock Operation, 16K/512 OTP, 7-channel 10-bit A/D, I²C, PWM, Capture/Compare, High I/O
footprint SOT314-2_N (Thin QFP, 64-Leads, Body 10x10mm, Pitch 0.5mm, IPC Medium Density)
footprint SOT314-2_L (Thin QFP, 64-Leads, Body 10x10mm, Pitch 0.5mm, IPC High Density)
footprint SOT314-2_M (Thin QFP, 64-Leads, Body 10x10mm, Pitch 0.5mm, IPC Low Density)
pins: 1 AVDD (power), 2 P5.6/ADC6 (in), 3 P5.5/ADC5 (in), 4 P5.4/ADC4 (in), 5 P5.3/ADC3 (in), 6 P5.2/ADC2 (in), 7 P5.1/ADC1 (in), 8 P5.0/ADC0 (in), 9 VDD (power), 10 STADC (in), 11 ~{PWM}0 (out), 12 ~{PWM}1 (out), 13 ~{EW} (in), 14 P4.0/CMSR0 (io), 15 P4.1/CMSR1 (io), 16 P4.2/CMSR2 (io), 17 P4.3/CMSR3 (io), 18 P4.4/CMSR4 (io), 19 P4.5/CMSR5 (io), 20 P4.6/CMT0 (io), 21 P4.7/CMT1 (io), 22 RST (io), 23 P1.0/CT0I (io), 24 P1.1/CT1I (io), 25 P1.2/CT2I (io), 26 P1.3/CT3I (io), 27 P1.4/T2 (io), 28 P1.5/RT2 (io), 29 P1.6/SCL (io), 30 P1.7/SDA (io), 31 P3.0/RxD (io), 32 P3.1/TxD (io), 33 P3.2/~{INT}0 (io), 34 P3.3/~{INT}1 (io), 35 P3.4/T0 (io), 36 P3.5/T1 (io), 37 P3.6/~{WR} (io), 38 P3.7/~{RD} (io), 39 XTAL2 (out), 40 XTAL1 (in), 41 VSS (power), 42 VSS (power), 43 P2.0/A08 (io), 44 P2.1/A09 (io), 45 P2.2/A10 (io), 46 P2.3/A11 (io), 47 P2.4/A12 (io), 48 P2.5/A13 (io), 49 P2.6/A14 (io), 50 P2.7/A15 (io), 51 ~{PSEN} (out), 52 ALE/~{PROG} (io), 53 ~{EA}/VPP (in), 54 P0.7/AD7 (io), 55 P0.6/AD6 (io), 56 P0.5/AD5 (io), 57 P0.4/AD4 (io), 58 P0.3/AD3 (io), 59 P0.2/AD2 (io), 60 P0.1/AD1 (io), 61 P0.0/AD0 (io), 62 AVREF- (in), 63 AVREF+ (in), 64 AVSS (power)

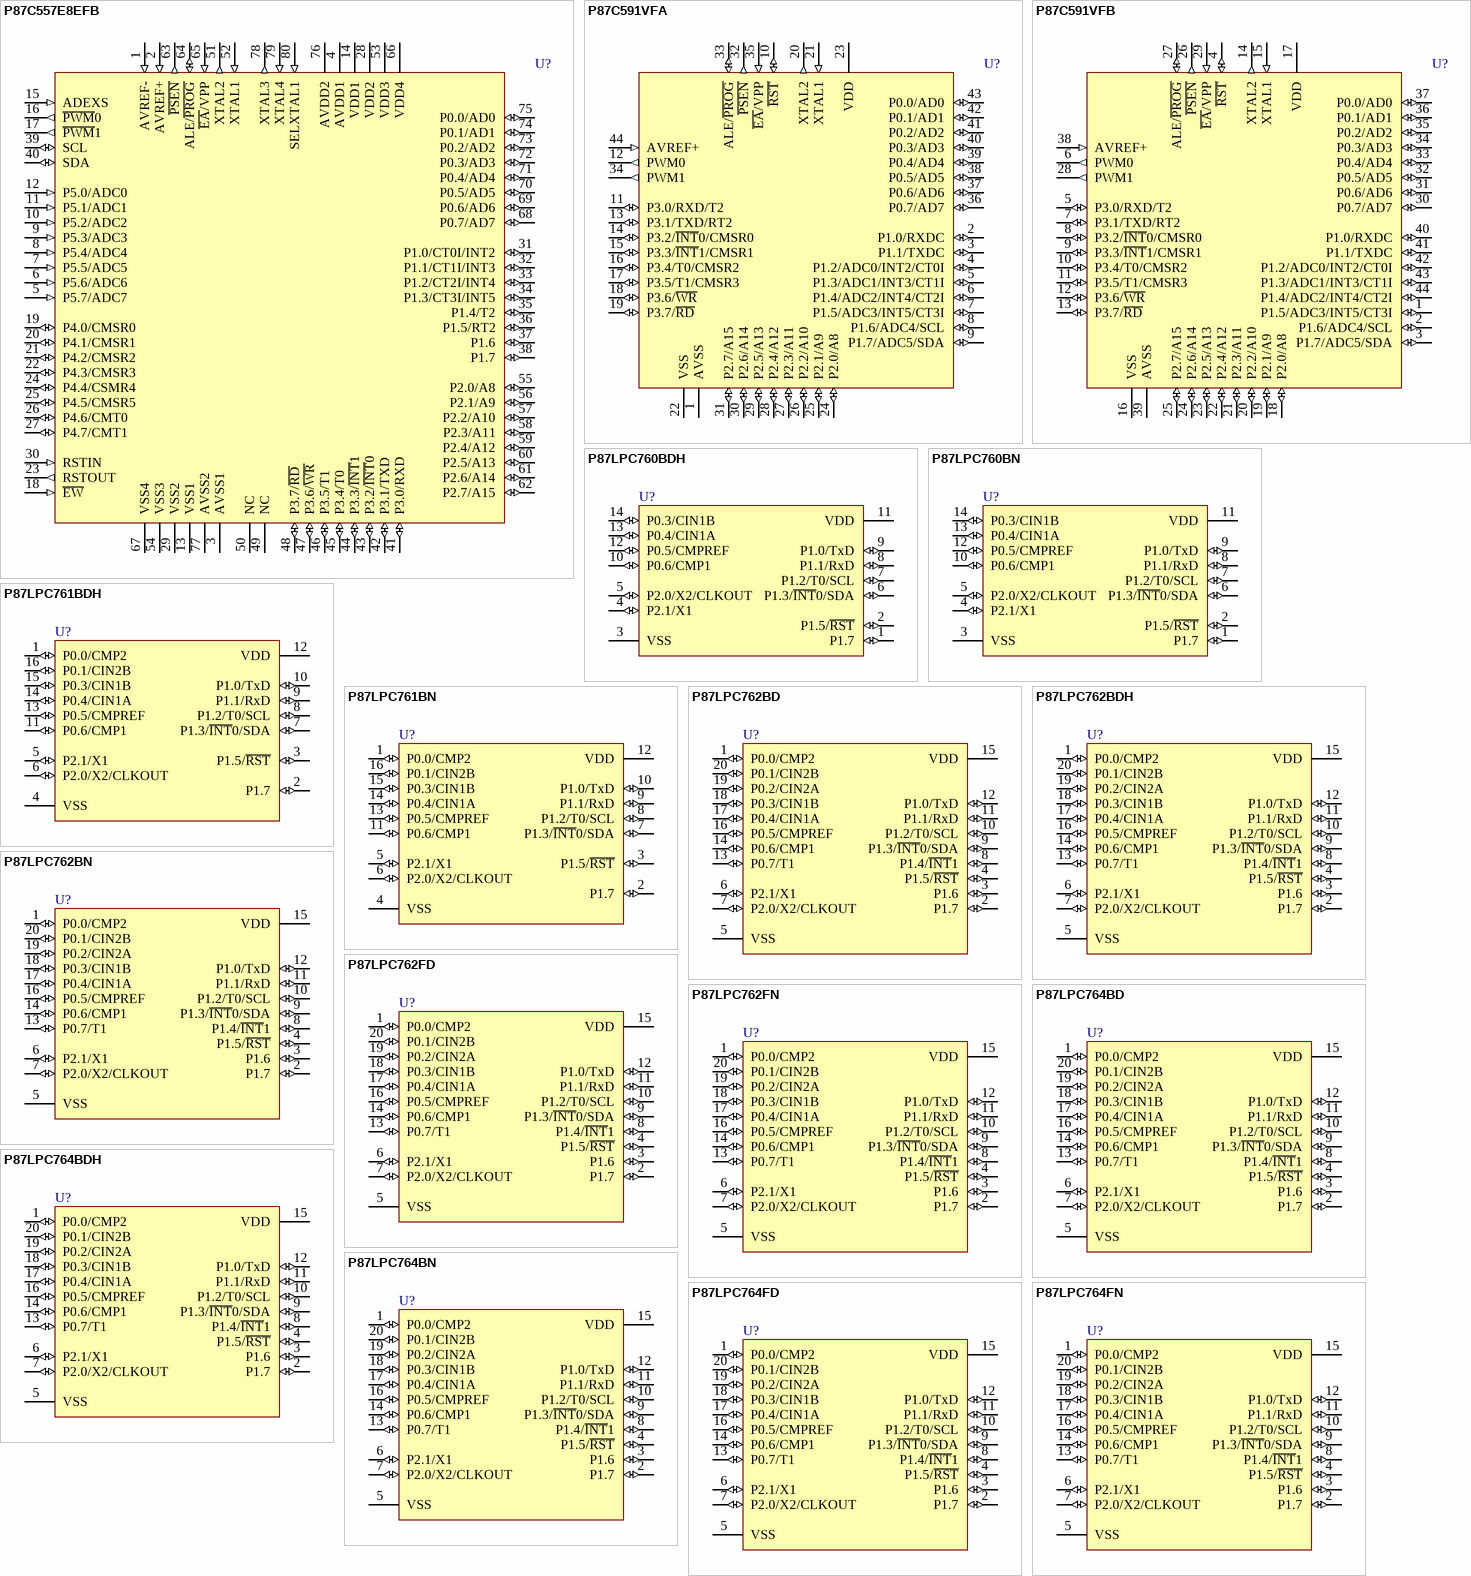
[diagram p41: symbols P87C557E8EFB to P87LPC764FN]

## P87C557E8EFB
designator U?
8-Bit Microcontroller, EPROM/OTP Type
footprint SOT318-2_N (QFP, 80-Leads, Body 20x14mm, Pitch 0.8mm, IPC Medium Density)
footprint SOT318-2_L (QFP, 80-Leads, Body 20x14mm, Pitch 0.8mm, IPC High Density)
footprint SOT318-2_M (QFP, 80-Leads, Body 20x14mm, Pitch 0.8mm, IPC Low Density)
pins: 1 AVREF- (in), 2 AVREF+ (in), 3 AVSS1 (power), 4 AVDD1 (power), 5 P5.7/ADC7 (in), 6 P5.6/ADC6 (in), 7 P5.5/ADC5 (in), 8 P5.4/ADC4 (in), 9 P5.3/ADC3 (in), 10 P5.2/ADC2 (in), 11 P5.1/ADC1 (in), 12 P5.0/ADC0 (in), 13 VSS1 (power), 14 VDD1 (power), 15 ADEXS (in), 16 ~{PWM}0 (out), 17 ~{PWM}1 (out), 18 ~{EW} (in), 19 P4.0/CMSR0 (io), 20 P4.1/CMSR1 (io), 21 P4.2/CMSR2 (io), 22 P4.3/CMSR3 (io), 23 RSTOUT (out), 24 P4.4/CSMR4 (io), 25 P4.5/CMSR5 (io), 26 P4.6/CMT0 (io), 27 P4.7/CMT1 (io), 28 VDD2 (power), 29 VSS2 (power), 30 RSTIN (in), 31 P1.0/CT0I/INT2 (io), 32 P1.1/CT1I/INT3 (io), 33 P1.2/CT2I/INT4 (io), 34 P1.3/CT3I/INT5 (io), 35 P1.4/T2 (io), 36 P1.5/RT2 (io), 37 P1.6 (io), 38 P1.7 (io), 39 SCL (io), 40 SDA (io), 41 P3.0/RXD (io), 42 P3.1/TXD (io), 43 P3.2/~{INT}0 (io), 44 P3.3/~{INT}1 (io), 45 P3.4/T0 (io), 46 P3.5/T1 (io), 47 P3.6/~{WR} (io), 48 P3.7/~{RD} (io), 49 NC, 50 NC, 51 XTAL2 (out), 52 XTAL1 (in), 53 VDD3 (power), 54 VSS3 (power), 55 P2.0/A8 (io), 56 P2.1/A9 (io), 57 P2.2/A10 (io), 58 P2.3/A11 (io), 59 P2.4/A12 (io), 60 P2.5/A13 (io), 61 P2.6/A14 (io), 62 P2.7/A15 (io), 63 ~{PSEN} (out), 64 ALE/~{PROG} (io), 65 ~{EA}/VPP (in), 66 VDD4 (power), 67 VSS4 (power), 68 P0.7/AD7 (io), 69 P0.6/AD6 (io), 70 P0.5/AD5 (io), 71 P0.4/AD4 (io), 72 P0.3/AD3 (io), 73 P0.2/AD2 (io), 74 P0.1/AD1 (io), 75 P0.0/AD0 (io), 76 AVDD2 (power), 77 AVSS2 (power), 78 XTAL3 (out), 79 XTAL4 (in), 80 SELXTAL1 (in)

## P87C591VFA
designator U?
Single-Chip 8-Bit Microcontroller with CAN Controller
footprint SOT187-2_N (Leaded Chip Carrier, 44-Leads, Body 16.6x16.6mm, Pitch 1.27mm, IPC Medium Density)
footprint SOT187-2_L (Leaded Chip Carrier, 44-Leads, Body 16.6x16.6mm, Pitch 1.27mm, IPC High Density)
footprint SOT187-2_M (Leaded Chip Carrier, 44-Leads, Body 16.6x16.6mm, Pitch 1.27mm, IPC Low Density)
pins: 1 AVSS (power), 2 P1.0/RXDC (io), 3 P1.1/TXDC (io), 4 P1.2/ADC0/INT2/CT0I (io), 5 P1.3/ADC1/INT3/CT1I (io), 6 P1.4/ADC2/INT4/CT2I (io), 7 P1.5/ADC3/INT5/CT3I (io), 8 P1.6/ADC4/SCL (io), 9 P1.7/ADC5/SDA (io), 10 ~{RST} (io), 11 P3.0/RXD/T2 (io), 12 PWM0 (out), 13 P3.1/TXD/RT2 (io), 14 P3.2/~{INT}0/CMSR0 (io), 15 P3.3/~{INT}1/CMSR1 (io), 16 P3.4/T0/CMSR2 (io), 17 P3.5/T1/CMSR3 (io), 18 P3.6/~{WR} (io), 19 P3.7/~{RD} (io), 20 XTAL2 (out), 21 XTAL1 (in), 22 VSS (power), 23 VDD (power), 24 P2.0/A8 (io), 25 P2.1/A9 (io), 26 P2.2/A10 (io), 27 P2.3/A11 (io), 28 P2.4/A12 (io), 29 P2.5/A13 (io), 30 P2.6/A14 (io), 31 P2.7/A15 (io), 32 ~{PSEN} (out), 33 ALE/~{PROG} (io), 34 PWM1 (out), 35 ~{EA}/VPP (in), 36 P0.7/AD7 (io), 37 P0.6/AD6 (io), 38 P0.5/AD5 (io), 39 P0.4/AD4 (io), 40 P0.3/AD3 (io), 41 P0.2/AD2 (io), 42 P0.1/AD1 (io), 43 P0.0/AD0 (io), 44 AVREF+ (in)

## P87C591VFB
designator U?
Single-Chip 8-Bit Microcontroller with CAN Controller
footprint SOT307-2_N (QFP, 44-Leads, Body 10x10mm, Pitch 0.8mm, IPC Medium Density)
footprint SOT307-2_L (QFP, 44-Leads, Body 10x10mm, Pitch 0.8mm, IPC High Density)
footprint SOT307-2_M (QFP, 44-Leads, Body 10x10mm, Pitch 0.8mm, IPC Low Density)
pins: 1 P1.5/ADC3/INT5/CT3I (io), 2 P1.6/ADC4/SCL (io), 3 P1.7/ADC5/SDA (io), 4 ~{RST} (io), 5 P3.0/RXD/T2 (io), 6 PWM0 (out), 7 P3.1/TXD/RT2 (io), 8 P3.2/~{INT}0/CMSR0 (io), 9 P3.3/~{INT}1/CMSR1 (io), 10 P3.4/T0/CMSR2 (io), 11 P3.5/T1/CMSR3 (io), 12 P3.6/~{WR} (io), 13 P3.7/~{RD} (io), 14 XTAL2 (out), 15 XTAL1 (in), 16 VSS (power), 17 VDD (power), 18 P2.0/A8 (io), 19 P2.1/A9 (io), 20 P2.2/A10 (io), 21 P2.3/A11 (io), 22 P2.4/A12 (io), 23 P2.5/A13 (io), 24 P2.6/A14 (io), 25 P2.7/A15 (io), 26 ~{PSEN} (out), 27 ALE/~{PROG} (io), 28 PWM1 (out), 29 ~{EA}/VPP (in), 30 P0.7/AD7 (io), 31 P0.6/AD6 (io), 32 P0.5/AD5 (io), 33 P0.4/AD4 (io), 34 P0.3/AD3 (io), 35 P0.2/AD2 (io), 36 P0.1/AD1 (io), 37 P0.0/AD0 (io), 38 AVREF+ (in), 39 AVSS (power), 40 P1.0/RXDC (io), 41 P1.1/TXDC (io), 42 P1.2/ADC0/INT2/CT0I (io), 43 P1.3/ADC1/INT3/CT1I (io), 44 P1.4/ADC2/INT4/CT2I (io)

## P87LPC760BDH
designator U?
Low Power, Low Price, Low Pin Count (14 pin) Microcontroller with 1 kB OTP
footprint SOT402-1 (Shrink Small Outline; 14 Leads; Body Width 4.4 mm; Pitch 0.65 mm)
pins: 1 P1.7 (io), 2 P1.5/~{RST} (io), 3 VSS (power), 4 P2.1/X1 (io), 5 P2.0/X2/CLKOUT (io), 6 P1.3/~{INT}0/SDA (io), 7 P1.2/T0/SCL (io), 8 P1.1/RxD (io), 9 P1.0/TxD (io), 10 P0.6/CMP1 (io), 11 VDD (power), 12 P0.5/CMPREF (io), 13 P0.4/CIN1A (io), 14 P0.3/CIN1B (io)

## P87LPC760BN
designator U?
Low Power, Low Price, Low Pin Count (14 pin) Microcontroller with 1 kB OTP
footprint SOT27-1 (DIP; 14 Leads; Row Spacing 7.62 mm; Pitch 2.54 mm)
pins: 1 P1.7 (io), 2 P1.5/~{RST} (io), 3 VSS (power), 4 P2.1/X1 (io), 5 P2.0/X2/CLKOUT (io), 6 P1.3/~{INT}0/SDA (io), 7 P1.2/T0/SCL (io), 8 P1.1/RxD (io), 9 P1.0/TxD (io), 10 P0.6/CMP1 (io), 11 VDD (power), 12 P0.5/CMPREF (io), 13 P0.4/CIN1A (io), 14 P0.3/CIN1B (io)

## P87LPC761BDH
designator U?
Low Power, Low Price, Low Pin Count (16 pin) Microcontroller with 2 kB OTP
footprint SOT403-1 (Shrink Small Outline; 16 Leads; Body Width 4.4 mm; Pitch 0.65 mm)
pins: 1 P0.0/CMP2 (io), 2 P1.7 (io), 3 P1.5/~{RST} (io), 4 VSS (power), 5 P2.1/X1 (io), 6 P2.0/X2/CLKOUT (io), 7 P1.3/~{INT}0/SDA (io), 8 P1.2/T0/SCL (io), 9 P1.1/RxD (io), 10 P1.0/TxD (io), 11 P0.6/CMP1 (io), 12 VDD (power), 13 P0.5/CMPREF (io), 14 P0.4/CIN1A (io), 15 P0.3/CIN1B (io), 16 P0.1/CIN2B (io)

## P87LPC761BN
designator U?
Low Power, Low Price, Low Pin Count (16 pin) Microcontroller with 2 kB OTP
footprint SOT38-1 (DIP; 16 Leads; Row Spacing 7.62 mm; Pitch 2.54 mm)
pins: 1 P0.0/CMP2 (io), 2 P1.7 (io), 3 P1.5/~{RST} (io), 4 VSS (power), 5 P2.1/X1 (io), 6 P2.0/X2/CLKOUT (io), 7 P1.3/~{INT}0/SDA (io), 8 P1.2/T0/SCL (io), 9 P1.1/RxD (io), 10 P1.0/TxD (io), 11 P0.6/CMP1 (io), 12 VDD (power), 13 P0.5/CMPREF (io), 14 P0.4/CIN1A (io), 15 P0.3/CIN1B (io), 16 P0.1/CIN2B (io)

## P87LPC762BD
designator U?
Low Power, Low Price, Low Pin Count (20 pin) Microcontroller with 2 kB OTP
footprint SOT163-1_N (SOIC, 20-Leads, Body 12.8x7.5mm, Pitch 1.27mm, IPC Medium Density)
footprint SOT163-1_L (SOIC, 20-Leads, Body 12.8x7.5mm, Pitch 1.27mm, IPC High Density)
footprint SOT163-1_M (SOIC, 20-Leads, Body 12.8x7.5mm, Pitch 1.27mm, IPC Low Density)
pins: 1 P0.0/CMP2 (io), 2 P1.7 (io), 3 P1.6 (io), 4 P1.5/~{RST} (io), 5 VSS (power), 6 P2.1/X1 (io), 7 P2.0/X2/CLKOUT (io), 8 P1.4/~{INT}1 (io), 9 P1.3/~{INT}0/SDA (io), 10 P1.2/T0/SCL (io), 11 P1.1/RxD (io), 12 P1.0/TxD (io), 13 P0.7/T1 (io), 14 P0.6/CMP1 (io), 15 VDD (power), 16 P0.5/CMPREF (io), 17 P0.4/CIN1A (io), 18 P0.3/CIN1B (io), 19 P0.2/CIN2A (io), 20 P0.1/CIN2B (io)

## P87LPC762BDH
designator U?
Low Power, Low Price, Low Pin Count (20 pin) Microcontroller with 2 kB OTP
footprint SOT360-1 (Shrink Small Outline; 20 Leads; Body Width 4.4 mm; Pitch 0.65 mm)
pins: 1 P0.0/CMP2 (io), 2 P1.7 (io), 3 P1.6 (io), 4 P1.5/~{RST} (io), 5 VSS (power), 6 P2.1/X1 (io), 7 P2.0/X2/CLKOUT (io), 8 P1.4/~{INT}1 (io), 9 P1.3/~{INT}0/SDA (io), 10 P1.2/T0/SCL (io), 11 P1.1/RxD (io), 12 P1.0/TxD (io), 13 P0.7/T1 (io), 14 P0.6/CMP1 (io), 15 VDD (power), 16 P0.5/CMPREF (io), 17 P0.4/CIN1A (io), 18 P0.3/CIN1B (io), 19 P0.2/CIN2A (io), 20 P0.1/CIN2B (io)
